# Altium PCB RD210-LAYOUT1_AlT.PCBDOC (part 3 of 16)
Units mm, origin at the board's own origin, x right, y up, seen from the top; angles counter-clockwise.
Board outline 330 x 300 mm, 6 copper layers (TOP, Mid-Layer 1, Mid-Layer 2, Mid-Layer 3, Mid-Layer 4, BOTTOM), stack 1.422 mm thick; 981 components, 463 nets, 2326 pads, 12534 vias.
Unrouted connection lines stored in the file: 6.
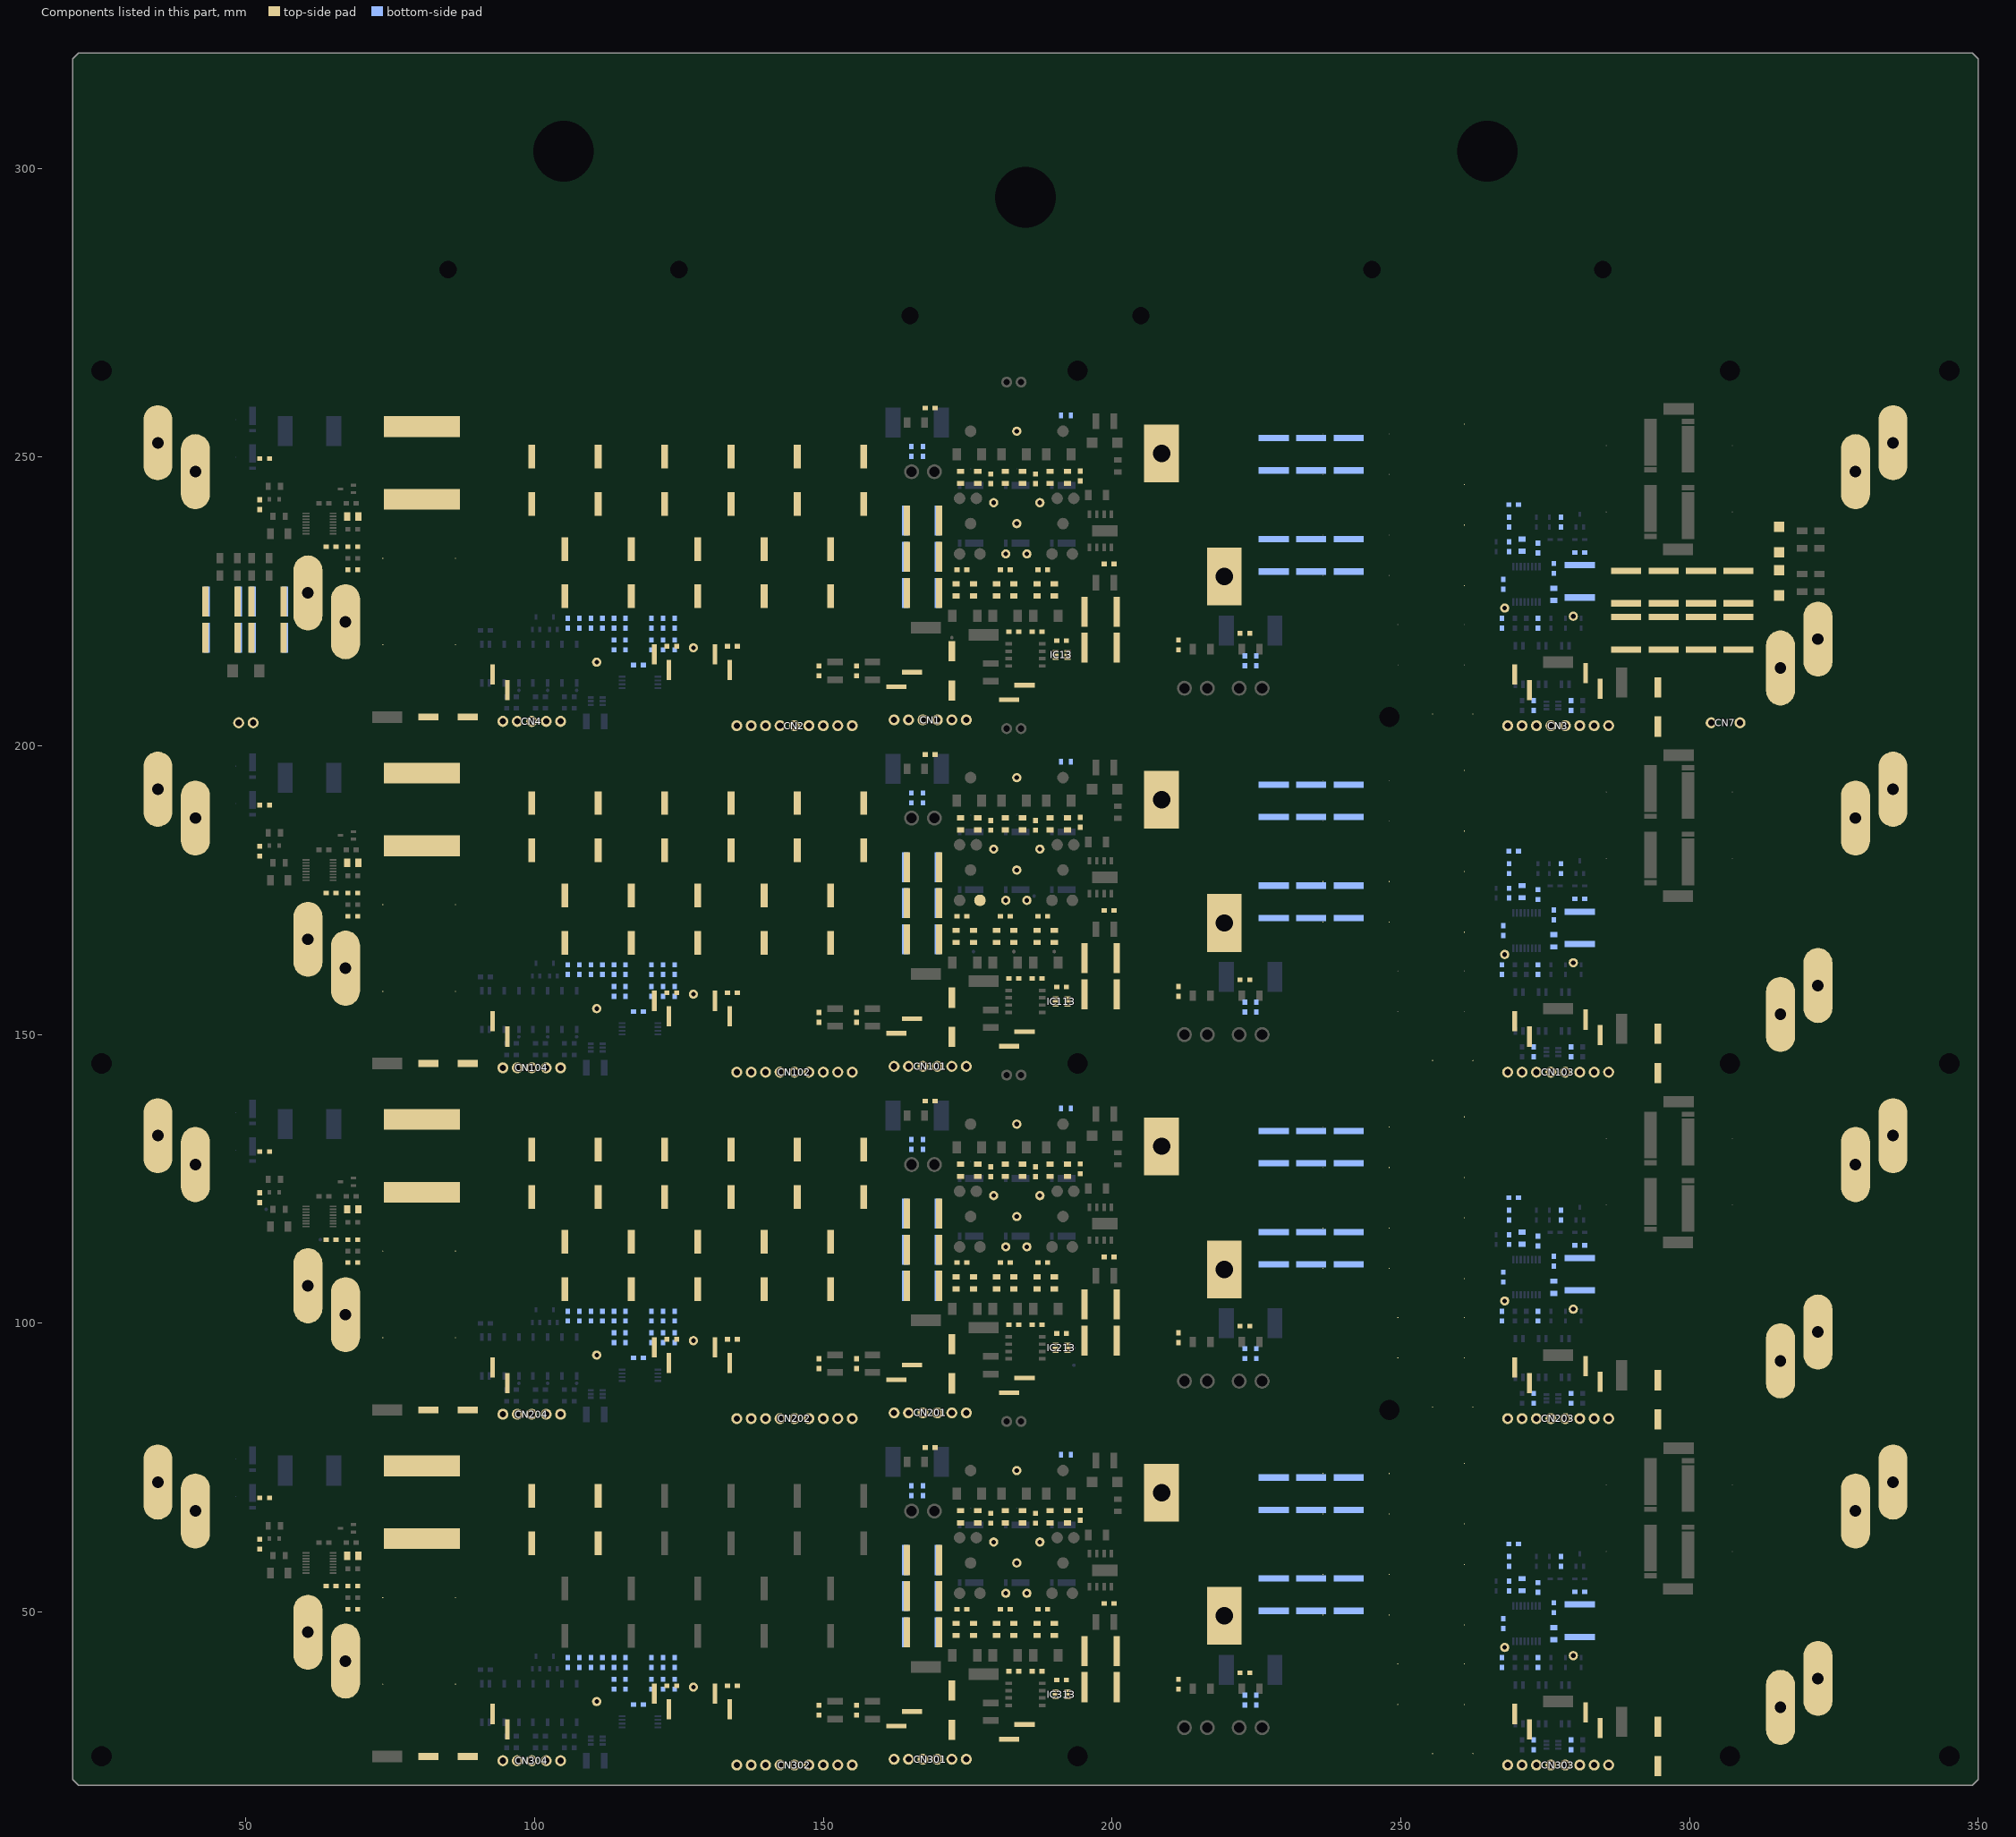
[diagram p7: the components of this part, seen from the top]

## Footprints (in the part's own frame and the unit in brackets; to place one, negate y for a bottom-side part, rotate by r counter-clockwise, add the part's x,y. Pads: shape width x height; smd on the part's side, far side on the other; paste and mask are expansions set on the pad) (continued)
_PCV1J390MCL2GS_+11 [mil] "KC00080BKP"
  round 7 smd paste-7 mask+0: 1(-137.8,0) 2(137.8,0)
_PCV1J390MCL2GS_+12 [mil] "KC00080BKP"
  round 7 smd paste-7 mask+0: 1(-137.8,0) 2(137.79,0)
_PCV1J390MCL2GS_+13 [mil] "KC00080BKP"
  round 7 smd paste-7 mask+0: 1(-137.8,0) 2(137.79,0)
_PCV1J390MCL2GS_+14 [mil] "KC00080BKP"
  round 7 smd paste-7 mask+0: 1(-137.79,0) 2(137.8,0)
_PCV1J390MCL2GS_+15 [mil] "KC00080BKP"
  round 7 smd paste-7 mask+0: 1(-137.79,0) 2(137.8,0)
_PCV1J390MCL2GS_+16 [mil] "KC00080BKP"
  round 7 smd paste-7 mask+0: 1(-137.79,0) 2(137.8,0)
_PCV1J390MCL2GS_+17 [mil] "KC00080BKP"
  round 7 smd paste-7 mask+0: 1(-137.79,0) 2(137.8,0)
_PCV1J390MCL2GS_+18 [mil] "KC00080BKP"
  round 7 smd paste-7 mask+0: 1(-137.79,0) 2(137.8,0)
_PCV1J390MCL2GS_+19 [mil] "KC00080BKP"
  round 7 smd paste-7 mask+0: 1(-137.79,0) 2(137.8,0)
_PCV1J390MCL2GS_+20 [mil] "KC00080BKP"
  round 7 smd paste-7 mask+0: 1(-137.79,0) 2(137.8,0)
_PCV1J390MCL2GS_+21 [mil] "KC00080BKP"
  round 7 smd paste-7 mask+0: 1(-137.79,0) 2(137.8,0)
_PCV1J390MCL2GS_+22 [mil] "KC00080BKP"
  round 7 smd paste-7 mask+0: 1(-137.8,0) 2(137.79,0)
_PCV1J390MCL2GS_+23 [mil] "KC00080BKP"
  round 7 smd paste-7 mask+0: 1(-137.8,0) 2(137.79,0)
_RK73B1JTTD103J_ [mm] "KC00080BKP"
  rect 0.9x0.8 smd paste-0.9 mask+0: 1(-0.85,0) 2(0.85,0)
_RK73B1JTTD103J_+1 [mm] "KC00080BKP"
  rect 0.9x0.8 smd paste-0.9 mask+0: 1(-0.85,0) 2(0.85,0)
_RK73B1JTTD103J_+2 [mm] "KC00080BKP"
  rect 0.9x0.8 smd paste-0.9 mask+0: 1(-0.85,0) 2(0.85,0)
_RK73B1JTTD103J_+3 [mm] "KC00080BKP"
  rect 0.9x0.8 smd paste-0.9 mask+0: 1(-0.85,0) 2(0.85,0)
_RK73B1JTTD103J_+4 [mm] "KC00080BKP"
  rect 0.9x0.8 smd paste-0.9 mask+0: 1(-0.85,0) 2(0.85,0)
_RK73B1JTTD103J_+5 [mm] "KC00080BKP"
  rect 0.9x0.8 smd paste-0.9 mask+0: 1(-0.85,0) 2(0.85,0)
_RK73B1JTTD103J_+6 [mm] "KC00080BKP"
  rect 0.9x0.8 smd paste-0.9 mask+0: 1(-0.85,0) 2(0.85,0)
_RK73B1JTTD103J_+7 [mm] "KC00080BKP"
  rect 0.9x0.8 smd paste-0.9 mask+0: 1(-0.85,0) 2(0.85,0)
_RK73B1JTTD103J_+8 [mm] "KC00080BKP"
  rect 0.9x0.8 smd paste-0.9 mask+0: 1(-0.85,0) 2(0.85,0)
_RK73B1JTTD103J_+9 [mm] "KC00080BKP"
  rect 0.9x0.8 smd paste-0.9 mask+0: 1(-0.85,0) 2(0.85,0)
_RK73B1JTTD103J_+10 [mm] "KC00080BKP"
  rect 0.9x0.8 smd paste-0.9 mask+0: 1(-0.85,0) 2(0.85,0)
_RK73B1JTTD103J_+11 [mm] "KC00080BKP"
  rect 0.9x0.8 smd paste-0.9 mask+0: 1(-0.85,0) 2(0.85,0)
_RK73B1JTTD103J_+12 [mm] "KC00080BKP"
  rect 0.9x0.8 smd paste-0.9 mask+0: 1(-0.85,0) 2(0.85,0)
_RK73B1JTTD103J_+13 [mm] "KC00080BKP"
  rect 0.9x0.8 smd paste-0.9 mask+0: 1(-0.85,0) 2(0.85,0)
_RK73B1JTTD103J_+14 [mm] "KC00080BKP"
  rect 0.9x0.8 smd paste-0.9 mask+0: 1(-0.85,0) 2(0.85,0)
_RK73B1JTTD103J_+15 [mm] "KC00080BKP"
  rect 0.9x0.8 smd paste-0.9 mask+0: 1(-0.85,0) 2(0.85,0)
_RK73B1JTTD103J_+16 [mm] "KC00080BKP"
  rect 0.9x0.8 smd paste-0.9 mask+0: 1(-0.85,0) 2(0.85,0)
_RK73B1JTTD103J_+17 [mm] "KC00080BKP"
  rect 0.9x0.8 smd paste-0.9 mask+0: 1(-0.85,0) 2(0.85,0)
_RK73B1JTTD103J_+18 [mm] "KC00080BKP"
  rect 0.9x0.8 smd paste-0.9 mask+0: 1(-0.85,0) 2(0.85,0)
_RK73B1JTTD103J_+19 [mm] "KC00080BKP"
  rect 0.9x0.8 smd paste-0.9 mask+0: 1(-0.85,0) 2(0.85,0)
_RK73B1JTTD103J_+20 [mm] "KC00080BKP"
  rect 0.9x0.8 smd paste-0.9 mask+0: 1(-0.85,0) 2(0.85,0)
_RK73B1JTTD103J_+21 [mm] "KC00080BKP"
  rect 0.9x0.8 smd paste-0.9 mask+0: 1(-0.85,0) 2(0.85,0)
_RK73B1JTTD103J_+22 [mm] "KC00080BKP"
  rect 0.9x0.8 smd paste-0.9 mask+0: 1(-0.85,0) 2(0.85,0)
_RK73B1JTTD103J_+23 [mm] "KC00080BKP"
  rect 0.9x0.8 smd paste-0.9 mask+0: 1(-0.85,0) 2(0.85,0)
_RK73B1JTTD222J_ [mm] "KC00080BKP"
  rect 0.9x0.8 smd paste-0.9 mask+0: 1(0.85,0) 2(-0.85,0)
_RK73B1JTTD222J_+1 [mm] "KC00080BKP"
  rect 0.9x0.8 smd paste-0.9 mask+0: 1(0.85,0) 2(-0.85,0)
_RK73B1JTTD222J_+2 [mm] "KC00080BKP"
  rect 0.9x0.8 smd paste-0.9 mask+0: 1(0.85,0) 2(-0.85,0)
_RK73B1JTTD222J_+3 [mm] "KC00080BKP"
  rect 0.9x0.8 smd paste-0.9 mask+0: 1(0.85,0) 2(-0.85,0)
_RK73B1JTTD222J_+4 [mm] "KC00080BKP"
  rect 0.9x0.8 smd paste-0.9 mask+0: 1(0.85,0) 2(-0.85,0)
_RK73B1JTTD222J_+5 [mm] "KC00080BKP"
  rect 0.9x0.8 smd paste-0.9 mask+0: 1(0.85,0) 2(-0.85,0)
_RK73B1JTTD222J_+6 [mm] "KC00080BKP"
  rect 0.9x0.8 smd paste-0.9 mask+0: 1(0.85,0) 2(-0.85,0)
_RK73B1JTTD222J_+7 [mm] "KC00080BKP"
  rect 0.9x0.8 smd paste-0.9 mask+0: 1(0.85,0) 2(-0.85,0)
_RK73B1JTTD334J_ [mm] "KC00080BKP"
  rect 0.9x0.8 smd paste-0.9 mask+0: 1(0.85,0) 2(-0.85,0)
_RK73B1JTTD334J_+1 [mm] "KC00080BKP"
  rect 0.9x0.8 smd paste-0.9 mask+0: 1(0.85,0) 2(-0.85,0)
_RK73B1JTTD334J_+2 [mm] "KC00080BKP"
  rect 0.9x0.8 smd paste-0.9 mask+0: 1(0.85,0) 2(-0.85,0)
_RK73B1JTTD334J_+3 [mm] "KC00080BKP"
  rect 0.9x0.8 smd paste-0.9 mask+0: 1(0.85,0) 2(-0.85,0)
_RK73B1JTTD473J_ [mm] "KC00080BKP"
  rect 0.9x0.8 smd paste-0.9 mask+0: 1(0.85,0) 2(-0.85,0)
_RK73B1JTTD473J_+1 [mm] "KC00080BKP"
  rect 0.9x0.8 smd paste-0.9 mask+0: 1(0.85,0) 2(-0.85,0)
_RK73B1JTTD473J_+2 [mm] "KC00080BKP"
  rect 0.9x0.8 smd paste-0.9 mask+0: 1(0.85,0) 2(-0.85,0)
_RK73B1JTTD473J_+3 [mm] "KC00080BKP"
  rect 0.9x0.8 smd paste-0.9 mask+0: 1(0.85,0) 2(-0.85,0)
_RK73B1JTTD473J_+4 [mm] "KC00080BKP"
  rect 0.9x0.8 smd paste-0.9 mask+0: 1(0.85,0) 2(-0.85,0)
_RK73B1JTTD473J_+5 [mm] "KC00080BKP"
  rect 0.9x0.8 smd paste-0.9 mask+0: 1(0.85,0) 2(-0.85,0)
_RK73B1JTTD473J_+6 [mm] "KC00080BKP"
  rect 0.9x0.8 smd paste-0.9 mask+0: 1(0.85,0) 2(-0.85,0)
_RK73B1JTTD473J_+7 [mm] "KC00080BKP"
  rect 0.9x0.8 smd paste-0.9 mask+0: 1(0.85,0) 2(-0.85,0)
_RK73G1JTTD10R0D_ [mm] "KC00080BKP"
  rect 0.9x0.8 smd paste-0.9 mask+0: 1(-0.85,0) 2(0.85,0)
_RK73G1JTTD10R0D_+1 [mm] "KC00080BKP"
  rect 0.9x0.8 smd paste-0.9 mask+0: 1(-0.85,0) 2(0.85,0)
_RK73G1JTTD10R0D_+2 [mm] "KC00080BKP"
  rect 0.9x0.8 smd paste-0.9 mask+0: 1(-0.85,0) 2(0.85,0)
_RK73G1JTTD10R0D_+3 [mm] "KC00080BKP"
  rect 0.9x0.8 smd paste-0.9 mask+0: 1(-0.85,0) 2(0.85,0)
_RK73G1JTTD10R0D_+4 [mm] "KC00080BKP"
  rect 0.9x0.8 smd paste-0.9 mask+0: 1(-0.85,0) 2(0.85,0)
_RK73G1JTTD10R0D_+5 [mm] "KC00080BKP"
  rect 0.9x0.8 smd paste-0.9 mask+0: 1(-0.85,0) 2(0.85,0)
_RK73G1JTTD10R0D_+6 [mm] "KC00080BKP"
  rect 0.9x0.8 smd paste-0.9 mask+0: 1(-0.85,0) 2(0.85,0)
_RK73G1JTTD10R0D_+7 [mm] "KC00080BKP"
  rect 0.9x0.8 smd paste-0.9 mask+0: 1(-0.85,0) 2(0.85,0)
_RK73G1JTTD1001D_ [mm] "KC00080BKP"
  rect 0.9x0.8 smd paste-0.9 mask+0: 1(0.85,0) 2(-0.85,0)
_RK73G1JTTD1001D_+1 [mm] "KC00080BKP"
  rect 0.9x0.8 smd paste-0.9 mask+0: 1(0.85,0) 2(-0.85,0)
_RK73G1JTTD1001D_+2 [mm] "KC00080BKP"
  rect 0.9x0.8 smd paste-0.9 mask+0: 1(0.85,0) 2(-0.85,0)
_RK73G1JTTD1001D_+3 [mm] "KC00080BKP"
  rect 0.9x0.8 smd paste-0.9 mask+0: 1(0.85,0) 2(-0.85,0)
_RK73G1JTTD1001D_+4 [mm] "KC00080BKP"
  rect 0.9x0.8 smd paste-0.9 mask+0: 1(0.85,0) 2(-0.85,0)
_RK73G1JTTD1001D_+5 [mm] "KC00080BKP"
  rect 0.9x0.8 smd paste-0.9 mask+0: 1(0.85,0) 2(-0.85,0)
_RK73G1JTTD1001D_+6 [mm] "KC00080BKP"
  rect 0.9x0.8 smd paste-0.9 mask+0: 1(0.85,0) 2(-0.85,0)
_RK73G1JTTD1001D_+7 [mm] "KC00080BKP"
  rect 0.9x0.8 smd paste-0.9 mask+0: 1(0.85,0) 2(-0.85,0)
_RK73G1JTTD1001D_+8 [mm] "KC00080BKP"
  rect 0.9x0.8 smd paste-0.9 mask+0: 1(0.85,0) 2(-0.85,0)
_RK73G1JTTD1001D_+9 [mm] "KC00080BKP"
  rect 0.9x0.8 smd paste-0.9 mask+0: 1(0.85,0) 2(-0.85,0)
_RK73G1JTTD1001D_+10 [mm] "KC00080BKP"
  rect 0.9x0.8 smd paste-0.9 mask+0: 1(0.85,0) 2(-0.85,0)
_RK73G1JTTD1001D_+11 [mm] "KC00080BKP"
  rect 0.9x0.8 smd paste-0.9 mask+0: 1(0.85,0) 2(-0.85,0)
_RK73G1JTTD1001D_+12 [mm] "KC00080BKP"
  rect 0.9x0.8 smd paste-0.9 mask+0: 1(0.85,0) 2(-0.85,0)
_RK73G1JTTD1001D_+13 [mm] "KC00080BKP"
  rect 0.9x0.8 smd paste-0.9 mask+0: 1(0.85,0) 2(-0.85,0)
_RK73G1JTTD1001D_+14 [mm] "KC00080BKP"
  rect 0.9x0.8 smd paste-0.9 mask+0: 1(0.85,0) 2(-0.85,0)
_RK73G1JTTD1001D_+15 [mm] "KC00080BKP"
  rect 0.9x0.8 smd paste-0.9 mask+0: 1(0.85,0) 2(-0.85,0)
_RK73G1JTTD1003D_ [mm] "KC00080BKP"
  rect 0.9x0.8 smd paste-0.9 mask+0: 1(-0.85,0) 2(0.85,0)
_RK73G1JTTD1003D_+1 [mm] "KC00080BKP"
  rect 0.9x0.8 smd paste-0.9 mask+0: 1(-0.85,0) 2(0.85,0)
_RK73G1JTTD1003D_+2 [mm] "KC00080BKP"
  rect 0.9x0.8 smd paste-0.9 mask+0: 1(-0.85,0) 2(0.85,0)
_RK73G1JTTD1003D_+3 [mm] "KC00080BKP"
  rect 0.9x0.8 smd paste-0.9 mask+0: 1(-0.85,0) 2(0.85,0)
_RK73G1JTTD1102D_ [mm] "KC00080BKP"
  rect 0.9x0.8 smd paste-0.9 mask+0: 1(0.85,0) 2(-0.85,0)
_RK73G1JTTD1102D_+1 [mm] "KC00080BKP"
  rect 0.9x0.8 smd paste-0.9 mask+0: 1(0.85,0) 2(-0.85,0)
_RK73G1JTTD1102D_+2 [mm] "KC00080BKP"
  rect 0.9x0.8 smd paste-0.9 mask+0: 1(0.85,0) 2(-0.85,0)
_RK73G1JTTD1102D_+3 [mm] "KC00080BKP"
  rect 0.9x0.8 smd paste-0.9 mask+0: 1(0.85,0) 2(-0.85,0)
_RK73G1JTTD1102D_+4 [mm] "KC00080BKP"
  rect 0.9x0.8 smd paste-0.9 mask+0: 1(0.85,0) 2(-0.85,0)
_RK73G1JTTD1102D_+5 [mm] "KC00080BKP"
  rect 0.9x0.8 smd paste-0.9 mask+0: 1(0.85,0) 2(-0.85,0)
_RK73G1JTTD1102D_+6 [mm] "KC00080BKP"
  rect 0.9x0.8 smd paste-0.9 mask+0: 1(0.85,0) 2(-0.85,0)
_RK73G1JTTD1102D_+7 [mm] "KC00080BKP"
  rect 0.9x0.8 smd paste-0.9 mask+0: 1(0.85,0) 2(-0.85,0)
_RK73G1JTTD1801D_ [mm] "KC00080BKP"
  rect 0.9x0.8 smd paste-0.9 mask+0: 1(-0.85,0) 2(0.85,0)
_RK73G1JTTD1801D_+1 [mm] "KC00080BKP"
  rect 0.9x0.8 smd paste-0.9 mask+0: 1(-0.85,0) 2(0.85,0)
_RK73G1JTTD1801D_+2 [mm] "KC00080BKP"
  rect 0.9x0.8 smd paste-0.9 mask+0: 1(-0.85,0) 2(0.85,0)
_RK73G1JTTD1801D_+3 [mm] "KC00080BKP"
  rect 0.9x0.8 smd paste-0.9 mask+0: 1(-0.85,0) 2(0.85,0)
_RK73G1JTTD2002D_ [mm] "KC00080BKP"
  rect 0.9x0.8 smd paste-0.9 mask+0: 1(0.85,0) 2(-0.85,0)
_RK73G1JTTD2002D_+1 [mm] "KC00080BKP"
  rect 0.9x0.8 smd paste-0.9 mask+0: 1(0.85,0) 2(-0.85,0)
_RK73G1JTTD2002D_+2 [mm] "KC00080BKP"
  rect 0.9x0.8 smd paste-0.9 mask+0: 1(0.85,0) 2(-0.85,0)
_RK73G1JTTD2002D_+3 [mm] "KC00080BKP"
  rect 0.9x0.8 smd paste-0.9 mask+0: 1(0.85,0) 2(-0.85,0)
_RK73G1JTTD2002D_+4 [mm] "KC00080BKP"
  rect 0.9x0.8 smd paste-0.9 mask+0: 1(0.85,0) 2(-0.85,0)
_RK73G1JTTD2002D_+5 [mm] "KC00080BKP"
  rect 0.9x0.8 smd paste-0.9 mask+0: 1(0.85,0) 2(-0.85,0)
_RK73G1JTTD2002D_+6 [mm] "KC00080BKP"
  rect 0.9x0.8 smd paste-0.9 mask+0: 1(0.85,0) 2(-0.85,0)
_RK73G1JTTD2002D_+7 [mm] "KC00080BKP"
  rect 0.9x0.8 smd paste-0.9 mask+0: 1(0.85,0) 2(-0.85,0)
_RK73G1JTTD2002D_+8 [mm] "KC00080BKP"
  rect 0.9x0.8 smd paste-0.9 mask+0: 1(0.85,0) 2(-0.85,0)
_RK73G1JTTD2002D_+9 [mm] "KC00080BKP"
  rect 0.9x0.8 smd paste-0.9 mask+0: 1(0.85,0) 2(-0.85,0)
_RK73G1JTTD2002D_+10 [mm] "KC00080BKP"
  rect 0.9x0.8 smd paste-0.9 mask+0: 1(0.85,0) 2(-0.85,0)
_RK73G1JTTD2002D_+11 [mm] "KC00080BKP"
  rect 0.9x0.8 smd paste-0.9 mask+0: 1(0.85,0) 2(-0.85,0)
_RK73G1JTTD2002D_+12 [mm] "KC00080BKP"
  rect 0.9x0.8 smd paste-0.9 mask+0: 1(0.85,0) 2(-0.85,0)
_RK73G1JTTD2002D_+13 [mm] "KC00080BKP"
  rect 0.9x0.8 smd paste-0.9 mask+0: 1(0.85,0) 2(-0.85,0)
_RK73G1JTTD2002D_+14 [mm] "KC00080BKP"
  rect 0.9x0.8 smd paste-0.9 mask+0: 1(0.85,0) 2(-0.85,0)
_RK73G1JTTD2002D_+15 [mm] "KC00080BKP"
  rect 0.9x0.8 smd paste-0.9 mask+0: 1(0.85,0) 2(-0.85,0)
_RK73H1JTTD1004F_ [mm] "KC00080BKP"
  rect 0.9x0.8 smd paste-0.9 mask+0: 1(-0.85,0) 2(0.85,0)
_RK73H1JTTD1004F_+1 [mm] "KC00080BKP"
  rect 0.9x0.8 smd paste-0.9 mask+0: 1(-0.85,0) 2(0.85,0)
_RK73H1JTTD1004F_+2 [mm] "KC00080BKP"
  rect 0.9x0.8 smd paste-0.9 mask+0: 1(-0.85,0) 2(0.85,0)
_RK73H1JTTD1004F_+3 [mm] "KC00080BKP"
  rect 0.9x0.8 smd paste-0.9 mask+0: 1(-0.85,0) 2(0.85,0)
_RK73H1JTTD3303F_ [mm] "KC00080BKP"
  rect 0.9x0.8 smd paste-0.9 mask+0: 1(0.85,0) 2(-0.85,0)
_RK73H1JTTD3303F_+1 [mm] "KC00080BKP"
  rect 0.9x0.8 smd paste-0.9 mask+0: 1(0.85,0) 2(-0.85,0)
_RK73H1JTTD3303F_+2 [mm] "KC00080BKP"
  rect 0.9x0.8 smd paste-0.9 mask+0: 1(0.85,0) 2(-0.85,0)
_RK73H1JTTD3303F_+3 [mm] "KC00080BKP"
  rect 0.9x0.8 smd paste-0.9 mask+0: 1(0.85,0) 2(-0.85,0)
_RK73H1JTTD6802F_ [mm] "KC00080BKP"
  rect 0.9x0.8 smd paste-0.9 mask+0: 1(-0.85,0) 2(0.85,0)
_RK73H1JTTD6802F_+1 [mm] "KC00080BKP"
  rect 0.9x0.8 smd paste-0.9 mask+0: 1(-0.85,0) 2(0.85,0)
_RK73H1JTTD6802F_+2 [mm] "KC00080BKP"
  rect 0.9x0.8 smd paste-0.9 mask+0: 1(-0.85,0) 2(0.85,0)
_RK73H1JTTD6802F_+3 [mm] "KC00080BKP"
  rect 0.9x0.8 smd paste-0.9 mask+0: 1(-0.85,0) 2(0.85,0)
_RK73Z1JTTD_ [mm] "KC00080BKP"
  rect 0.9x0.8 smd paste-0.9 mask+0: 1(-0.85,0) 2(0.85,0)
_RK73Z1JTTD_+1 [mm] "KC00080BKP"
  rect 0.9x0.8 smd paste-0.9 mask+0: 1(-0.85,0) 2(0.85,0)
_RK73Z1JTTD_+2 [mm] "KC00080BKP"
  rect 0.9x0.8 smd paste-0.9 mask+0: 1(-0.85,0) 2(0.85,0)
_RK73Z1JTTD_+3 [mm] "KC00080BKP"
  rect 0.9x0.8 smd paste-0.9 mask+0: 1(-0.85,0) 2(0.85,0)
_RK73Z1JTTD_+4 [mm] "KC00080BKP"
  rect 0.9x0.8 smd paste-0.9 mask+0: 1(-0.85,0) 2(0.85,0)
_RK73Z1JTTD_+5 [mm] "KC00080BKP"
  rect 0.9x0.8 smd paste-0.9 mask+0: 1(-0.85,0) 2(0.85,0)
_RK73Z1JTTD_+6 [mm] "KC00080BKP"
  rect 0.9x0.8 smd paste-0.9 mask+0: 1(-0.85,0) 2(0.85,0)
_RK73Z1JTTD_+7 [mm] "KC00080BKP"
  rect 0.9x0.8 smd paste-0.9 mask+0: 1(-0.85,0) 2(0.85,0)
_SG73P1JTTD473J_ [mm] "KC00080BKP"
  rect 0.9x0.8 smd paste-0.9 mask+0: 1(0.85,0) 2(-0.85,0)
_SG73P1JTTD473J_+1 [mm] "KC00080BKP"
  rect 0.9x0.8 smd paste-0.9 mask+0: 1(0.85,0) 2(-0.85,0)
_SG73P1JTTD473J_+2 [mm] "KC00080BKP"
  rect 0.9x0.8 smd paste-0.9 mask+0: 1(0.85,0) 2(-0.85,0)
_SG73P1JTTD473J_+3 [mm] "KC00080BKP"
  rect 0.9x0.8 smd paste-0.9 mask+0: 1(0.85,0) 2(-0.85,0)
_SG73P1JTTD473J_+4 [mm] "KC00080BKP"
  rect 0.9x0.8 smd paste-0.9 mask+0: 1(0.85,0) 2(-0.85,0)
_SG73P1JTTD473J_+5 [mm] "KC00080BKP"
  rect 0.9x0.8 smd paste-0.9 mask+0: 1(0.85,0) 2(-0.85,0)
_SG73P1JTTD473J_+6 [mm] "KC00080BKP"
  rect 0.9x0.8 smd paste-0.9 mask+0: 1(0.85,0) 2(-0.85,0)
_SG73P1JTTD473J_+7 [mm] "KC00080BKP"
  rect 0.9x0.8 smd paste-0.9 mask+0: 1(0.85,0) 2(-0.85,0)
_SG73P2ATTD1R0J_ [mm] "KC00080BKP"
  rect 0.9x1.25 smd paste-1.25 mask+0: 1(-1.05,0) 2(1.05,0)
_SG73P2ATTD1R0J_+1 [mm] "KC00080BKP"
  rect 0.9x1.25 smd paste-1.25 mask+0: 1(-1.05,0) 2(1.05,0)
_SG73P2ATTD1R0J_+2 [mm] "KC00080BKP"
  rect 0.9x1.25 smd paste-1.25 mask+0: 1(-1.05,0) 2(1.05,0)
_SG73P2ATTD1R0J_+3 [mm] "KC00080BKP"
  rect 0.9x1.25 smd paste-1.25 mask+0: 1(-1.05,0) 2(1.05,0)
_SG73P2ATTD1R0J_+4 [mm] "KC00080BKP"
  rect 0.9x1.25 smd paste-1.25 mask+0: 1(-1.05,0) 2(1.05,0)
_SG73P2ATTD1R0J_+5 [mm] "KC00080BKP"
  rect 0.9x1.25 smd paste-1.25 mask+0: 1(-1.05,0) 2(1.05,0)
_SG73P2ATTD1R0J_+6 [mm] "KC00080BKP"
  rect 0.9x1.25 smd paste-1.25 mask+0: 1(-1.05,0) 2(1.05,0)
_SG73P2ATTD1R0J_+7 [mm] "KC00080BKP"
  rect 0.9x1.25 smd paste-1.25 mask+0: 1(-1.05,0) 2(1.05,0)
_SG73P2ATTD1R0J_+8 [mm] "KC00080BKP"
  rect 0.9x1.25 smd paste-1.25 mask+0: 1(-1.05,0) 2(1.05,0)
_SG73P2ATTD1R0J_+9 [mm] "KC00080BKP"
  rect 0.9x1.25 smd paste-1.25 mask+0: 1(-1.05,0) 2(1.05,0)
_SG73P2ATTD1R0J_+10 [mm] "KC00080BKP"
  rect 0.9x1.25 smd paste-1.25 mask+0: 1(-1.05,0) 2(1.05,0)
_SG73P2ATTD1R0J_+11 [mm] "KC00080BKP"
  rect 0.9x1.25 smd paste-1.25 mask+0: 1(-1.05,0) 2(1.05,0)
_SG73P2ATTD1R0J_+12 [mm] "KC00080BKP"
  rect 0.9x1.25 smd paste-1.25 mask+0: 1(-1.05,0) 2(1.05,0)
_SG73P2ATTD1R0J_+13 [mm] "KC00080BKP"
  rect 0.9x1.25 smd paste-1.25 mask+0: 1(-1.05,0) 2(1.05,0)
_SG73P2ATTD1R0J_+14 [mm] "KC00080BKP"
  rect 0.9x1.25 smd paste-1.25 mask+0: 1(-1.05,0) 2(1.05,0)
_SG73P2ATTD1R0J_+15 [mm] "KC00080BKP"
  rect 0.9x1.25 smd paste-1.25 mask+0: 1(-1.05,0) 2(1.05,0)
_SG73P2ATTD1R0J_+16 [mm] "KC00080BKP"
  rect 0.9x1.25 smd paste-1.25 mask+0: 1(-1.05,0) 2(1.05,0)
_SG73P2ATTD1R0J_+17 [mm] "KC00080BKP"
  rect 0.9x1.25 smd paste-1.25 mask+0: 1(-1.05,0) 2(1.05,0)
_SG73P2ATTD1R0J_+18 [mm] "KC00080BKP"
  rect 0.9x1.25 smd paste-1.25 mask+0: 1(-1.05,0) 2(1.05,0)
_SG73P2ATTD1R0J_+19 [mm] "KC00080BKP"
  rect 0.9x1.25 smd paste-1.25 mask+0: 1(-1.05,0) 2(1.05,0)
_SG73P2ATTD1R0J_+20 [mm] "KC00080BKP"
  rect 0.9x1.25 smd paste-1.25 mask+0: 1(-1.05,0) 2(1.05,0)
_SG73P2ATTD1R0J_+21 [mm] "KC00080BKP"
  rect 0.9x1.25 smd paste-1.25 mask+0: 1(-1.05,0) 2(1.05,0)
_SG73P2ATTD1R0J_+22 [mm] "KC00080BKP"
  rect 0.9x1.25 smd paste-1.25 mask+0: 1(-1.05,0) 2(1.05,0)
_SG73P2ATTD1R0J_+23 [mm] "KC00080BKP"
  rect 0.9x1.25 smd paste-1.25 mask+0: 1(-1.05,0) 2(1.05,0)
_SG73P2ATTD2R2J_ [mm] "KC00080BKP"
  rect 0.9x1.25 smd paste-1.25 mask+0: 1(1.05,0) 2(-1.05,0)
_SG73P2ATTD2R2J_+1 [mm] "KC00080BKP"
  rect 0.9x1.25 smd paste-1.25 mask+0: 1(1.05,0) 2(-1.05,0)
_SG73P2ATTD2R2J_+2 [mm] "KC00080BKP"
  rect 0.9x1.25 smd paste-1.25 mask+0: 1(1.05,0) 2(-1.05,0)
_SG73P2ATTD2R2J_+3 [mm] "KC00080BKP"
  rect 0.9x1.25 smd paste-1.25 mask+0: 1(1.05,0) 2(-1.05,0)
_SG73P2ATTD100J_ [mm] "KC00080BKP"
  rect 0.9x1.25 smd paste-1.25 mask+0: 1(-1.05,0) 2(1.05,0)
_SG73P2ATTD100J_+1 [mm] "KC00080BKP"
  rect 0.9x1.25 smd paste-1.25 mask+0: 1(-1.05,0) 2(1.05,0)
_SG73P2ATTD100J_+2 [mm] "KC00080BKP"
  rect 0.9x1.25 smd paste-1.25 mask+0: 1(-1.05,0) 2(1.05,0)
_SG73P2ATTD100J_+3 [mm] "KC00080BKP"
  rect 0.9x1.25 smd paste-1.25 mask+0: 1(-1.05,0) 2(1.05,0)
_SG73P2ATTD100J_+4 [mm] "KC00080BKP"
  rect 0.9x1.25 smd paste-1.25 mask+0: 1(-1.05,0) 2(1.05,0)
_SG73P2ATTD100J_+5 [mm] "KC00080BKP"
  rect 0.9x1.25 smd paste-1.25 mask+0: 1(-1.05,0) 2(1.05,0)
_SG73P2ATTD100J_+6 [mm] "KC00080BKP"
  rect 0.9x1.25 smd paste-1.25 mask+0: 1(-1.05,0) 2(1.05,0)
_SG73P2ATTD100J_+7 [mm] "KC00080BKP"
  rect 0.9x1.25 smd paste-1.25 mask+0: 1(-1.05,0) 2(1.05,0)
_SG73P2ATTD100J_+8 [mm] "KC00080BKP"
  rect 0.9x1.25 smd paste-1.25 mask+0: 1(-1.05,0) 2(1.05,0)
_SG73P2ATTD100J_+9 [mm] "KC00080BKP"
  rect 0.9x1.25 smd paste-1.25 mask+0: 1(-1.05,0) 2(1.05,0)
_SG73P2ATTD100J_+10 [mm] "KC00080BKP"
  rect 0.9x1.25 smd paste-1.25 mask+0: 1(-1.05,0) 2(1.05,0)
_SG73P2ATTD100J_+11 [mm] "KC00080BKP"
  rect 0.9x1.25 smd paste-1.25 mask+0: 1(-1.05,0) 2(1.05,0)
_SG73P2ATTD100J_+12 [mm] "KC00080BKP"
  rect 0.9x1.25 smd paste-1.25 mask+0: 1(-1.05,0) 2(1.05,0)
_SG73P2ATTD100J_+13 [mm] "KC00080BKP"
  rect 0.9x1.25 smd paste-1.25 mask+0: 1(-1.05,0) 2(1.05,0)
_SG73P2ATTD100J_+14 [mm] "KC00080BKP"
  rect 0.9x1.25 smd paste-1.25 mask+0: 1(-1.05,0) 2(1.05,0)
_SG73P2ATTD100J_+15 [mm] "KC00080BKP"
  rect 0.9x1.25 smd paste-1.25 mask+0: 1(-1.05,0) 2(1.05,0)
_SG73P2ATTD100J_+16 [mm] "KC00080BKP"
  rect 0.9x1.25 smd paste-1.25 mask+0: 1(-1.05,0) 2(1.05,0)
_SG73P2ATTD100J_+17 [mm] "KC00080BKP"
  rect 0.9x1.25 smd paste-1.25 mask+0: 1(-1.05,0) 2(1.05,0)
_SG73P2ATTD100J_+18 [mm] "KC00080BKP"
  rect 0.9x1.25 smd paste-1.25 mask+0: 1(-1.05,0) 2(1.05,0)
_SG73P2ATTD100J_+19 [mm] "KC00080BKP"
  rect 0.9x1.25 smd paste-1.25 mask+0: 1(-1.05,0) 2(1.05,0)
_SG73P2ATTD100J_+20 [mm] "KC00080BKP"
  rect 0.9x1.25 smd paste-1.25 mask+0: 1(-1.05,0) 2(1.05,0)
_SG73P2ATTD100J_+21 [mm] "KC00080BKP"
  rect 0.9x1.25 smd paste-1.25 mask+0: 1(-1.05,0) 2(1.05,0)
_SG73P2ATTD100J_+22 [mm] "KC00080BKP"
  rect 0.9x1.25 smd paste-1.25 mask+0: 1(-1.05,0) 2(1.05,0)
_SG73P2ATTD100J_+23 [mm] "KC00080BKP"
  rect 0.9x1.25 smd paste-1.25 mask+0: 1(-1.05,0) 2(1.05,0)
_SG73P2ATTD912J_ [mm] "KC00080BKP"
  rect 0.9x1.25 smd paste-1.25 mask+0: 1(1.05,0) 2(-1.05,0)
_SG73P2ATTD912J_+1 [mm] "KC00080BKP"
  rect 0.9x1.25 smd paste-1.25 mask+0: 1(1.05,0) 2(-1.05,0)
_SG73P2ATTD912J_+2 [mm] "KC00080BKP"
  rect 0.9x1.25 smd paste-1.25 mask+0: 1(1.05,0) 2(-1.05,0)
_SG73P2ATTD912J_+3 [mm] "KC00080BKP"
  rect 0.9x1.25 smd paste-1.25 mask+0: 1(1.05,0) 2(-1.05,0)
_SZ1SMA24AT3G_ [mm] "KC00080BKP"
  rect 1.8x1.8 smd paste-1.8 mask+0: 1(-2.2,0) 2(2.2,0)
_SZ1SMA24AT3G_+1 [mm] "KC00080BKP"
  rect 1.8x1.8 smd paste-1.8 mask+0: 1(-2.2,0) 2(2.2,0)
_TC7PZ17FU_ [mm] "KC00080BKP"
  rect 0.45x1.05 smd paste-1.05 mask+0: 1(-0.65,-1.025) 2(0,-1.025) 3(0.65,-1.025) 4(0.65,1.025) 5(0,1.025) 6(-0.65,1.025)
_TC7PZ17FU_+1 [mm] "KC00080BKP"
  rect 0.45x1.05 smd paste-1.05 mask+0: 1(-0.65,-1.025) 2(0,-1.025) 3(0.65,-1.025) 4(0.65,1.025) 5(0,1.025) 6(-0.65,1.025)
_TC7PZ17FU_+2 [mm] "KC00080BKP"
  rect 0.45x1.05 smd paste-1.05 mask+0: 1(-0.65,-1.025) 2(0,-1.025) 3(0.65,-1.025) 4(0.65,1.025) 5(0,1.025) 6(-0.65,1.025)
_TC7PZ17FU_+3 [mm] "KC00080BKP"
  rect 0.45x1.05 smd paste-1.05 mask+0: 1(-0.65,-1.025) 2(0,-1.025) 3(0.65,-1.025) 4(0.65,1.025) 5(0,1.025) 6(-0.65,1.025)
_TD11-3H103FT_ [mm] "KC00080BKP"
  rect 0.7x1 smd paste-1 mask+0: 1(0.85,0) 2(-0.85,0)
_TD11-3H103FT_+1 [mm] "KC00080BKP"
  rect 0.7x1 smd paste-1 mask+0: 1(0.85,0) 2(-0.85,0)
_TD11-3H103FT_+2 [mm] "KC00080BKP"
  rect 0.7x1 smd paste-1 mask+0: 1(0.85,0) 2(-0.85,0)
_TD11-3H103FT_+3 [mm] "KC00080BKP"
  rect 0.7x1 smd paste-1 mask+0: 1(0.85,0) 2(-0.85,0)
_TSM-102-01-L-SV_ [mm] "KC00080BKP"
  rect 0.8x3.5 smd paste-3.5 mask+0: 1(-1.27,1.35) 2(1.27,-1.35)
_TSM-102-01-L-SV_+1 [mm] "KC00080BKP"
  rect 0.8x3.5 smd paste-3.5 mask+0: 1(-1.27,1.35) 2(1.27,-1.35)
_TSM-102-01-L-SV_+2 [mm] "KC00080BKP"
  rect 0.8x3.5 smd paste-3.5 mask+0: 1(-1.27,1.35) 2(1.27,-1.35)
_TSM-102-01-L-SV_+3 [mm] "KC00080BKP"
  rect 0.8x3.5 smd paste-3.5 mask+0: 1(-1.27,1.35) 2(1.27,-1.35)
_TSM-102-01-L-SV_+4 [mm] "KC00080BKP"
  rect 0.8x3.5 smd paste-3.5 mask+0: 1(-1.27,1.35) 2(1.27,-1.35)
_TSM-102-01-L-SV_+5 [mm] "KC00080BKP"
  rect 0.8x3.5 smd paste-3.5 mask+0: 1(-1.27,1.35) 2(1.27,-1.35)
_TSM-102-01-L-SV_+6 [mm] "KC00080BKP"
  rect 0.8x3.5 smd paste-3.5 mask+0: 1(-1.27,1.35) 2(1.27,-1.35)
_TSM-102-01-L-SV_+7 [mm] "KC00080BKP"
  rect 0.8x3.5 smd paste-3.5 mask+0: 1(-1.27,1.35) 2(1.27,-1.35)
_TSM-102-01-L-SV_+8 [mm] "KC00080BKP"
  rect 0.8x3.5 smd paste-3.5 mask+0: 1(-1.27,1.35) 2(1.27,-1.35)
_TSM-102-01-L-SV_+9 [mm] "KC00080BKP"
  rect 0.8x3.5 smd paste-3.5 mask+0: 1(-1.27,1.35) 2(1.27,-1.35)
_TSM-102-01-L-SV_+10 [mm] "KC00080BKP"
  rect 0.8x3.5 smd paste-3.5 mask+0: 1(-1.27,1.35) 2(1.27,-1.35)
_TSM-102-01-L-SV_+11 [mm] "KC00080BKP"
  rect 0.8x3.5 smd paste-3.5 mask+0: 1(-1.27,1.35) 2(1.27,-1.35)
_TSM-102-01-L-SV_+12 [mm] "KC00080BKP"
  rect 0.8x3.5 smd paste-3.5 mask+0: 1(-1.27,1.35) 2(1.27,-1.35)
_TSM-102-01-L-SV_+13 [mm] "KC00080BKP"
  rect 0.8x3.5 smd paste-3.5 mask+0: 1(-1.27,1.35) 2(1.27,-1.35)
_TSM-102-01-L-SV_+14 [mm] "KC00080BKP"
  rect 0.8x3.5 smd paste-3.5 mask+0: 1(-1.27,1.35) 2(1.27,-1.35)
_TSM-102-01-L-SV_+15 [mm] "KC00080BKP"
  rect 0.8x3.5 smd paste-3.5 mask+0: 1(-1.27,1.35) 2(1.27,-1.35)
_TSM-102-01-L-SV_+16 [mm] "KC00080BKP"
  rect 0.8x3.5 smd paste-3.5 mask+0: 1(-1.27,1.35) 2(1.27,-1.35)
_TSM-102-01-L-SV_+17 [mm] "KC00080BKP"
  rect 0.8x3.5 smd paste-3.5 mask+0: 1(-1.27,1.35) 2(1.27,-1.35)
_TSM-102-01-L-SV_+18 [mm] "KC00080BKP"
  rect 0.8x3.5 smd paste-3.5 mask+0: 1(-1.27,1.35) 2(1.27,-1.35)
_TSM-102-01-L-SV_+19 [mm] "KC00080BKP"
  rect 0.8x3.5 smd paste-3.5 mask+0: 1(-1.27,1.35) 2(1.27,-1.35)
_TSM-102-01-L-SV_+20 [mm] "KC00080BKP"
  rect 0.8x3.5 smd paste-3.5 mask+0: 1(-1.27,1.35) 2(1.27,-1.35)
_TSM-102-01-L-SV_+21 [mm] "KC00080BKP"
  rect 0.8x3.5 smd paste-3.5 mask+0: 1(-1.27,1.35) 2(1.27,-1.35)
_TSM-102-01-L-SV_+22 [mm] "KC00080BKP"
  rect 0.8x3.5 smd paste-3.5 mask+0: 1(-1.27,1.35) 2(1.27,-1.35)
_TSM-102-01-L-SV_+23 [mm] "KC00080BKP"
  rect 0.8x3.5 smd paste-3.5 mask+0: 1(-1.27,1.35) 2(1.27,-1.35)
_TSM-102-01-L-SV_+24 [mm] "KC00080BKP"
  rect 0.8x3.5 smd paste-3.5 mask+0: 1(-1.27,1.35) 2(1.27,-1.35)
_TSM-102-01-L-SV_+25 [mm] "KC00080BKP"
  rect 0.8x3.5 smd paste-3.5 mask+0: 1(-1.27,1.35) 2(1.27,-1.35)
_TSM-102-01-L-SV_+26 [mm] "KC00080BKP"
  rect 0.8x3.5 smd paste-3.5 mask+0: 1(-1.27,1.35) 2(1.27,-1.35)
_TSM-102-01-L-SV_+27 [mm] "KC00080BKP"
  rect 0.8x3.5 smd paste-3.5 mask+0: 1(-1.27,1.35) 2(1.27,-1.35)
_TSW-101-07-G-S_ [mm] "KC00080BKP"
  round 1.6 hole 0.8 paste-1.7 mask+0: 1(0,0)
_UCZ1A221MCL1GS_ [mm] "KC00080BKP"
  rect 3.5x1.2 smd paste-3.5 mask+0: 1(-3.4,0) 2(3.4,0)
_UCZ1A221MCL1GS_+1 [mm] "KC00080BKP"
  rect 3.5x1.2 smd paste-3.5 mask+0: 1(-3.4,0) 2(3.4,0)
_UCZ1A221MCL1GS_+2 [mm] "KC00080BKP"
  rect 3.5x1.2 smd paste-3.5 mask+0: 1(-3.4,0) 2(3.4,0)
_UCZ1A221MCL1GS_+3 [mm] "KC00080BKP"
  rect 3.5x1.2 smd paste-3.5 mask+0: 1(-3.4,0) 2(3.4,0)
_UCZ1A221MCL1GS_+4 [mm] "KC00080BKP"
  rect 3.5x1.2 smd paste-3.5 mask+0: 1(-3.4,0) 2(3.4,0)
_UCZ1A221MCL1GS_+5 [mm] "KC00080BKP"
  rect 3.5x1.2 smd paste-3.5 mask+0: 1(-3.4,0) 2(3.4,0)
_UCZ1A221MCL1GS_+6 [mm] "KC00080BKP"
  rect 3.5x1.2 smd paste-3.5 mask+0: 1(-3.4,0) 2(3.4,0)
_UCZ1A221MCL1GS_+7 [mm] "KC00080BKP"
  rect 3.5x1.2 smd paste-3.5 mask+0: 1(-3.4,0) 2(3.4,0)
_UCZ1A221MCL1GS_+8 [mm] "KC00080BKP"
  rect 3.5x1.2 smd paste-3.5 mask+0: 1(-3.4,0) 2(3.4,0)
_UCZ1A221MCL1GS_+9 [mm] "KC00080BKP"
  rect 3.5x1.2 smd paste-3.5 mask+0: 1(-3.4,0) 2(3.4,0)
_UCZ1A221MCL1GS_+10 [mm] "KC00080BKP"
  rect 3.5x1.2 smd paste-3.5 mask+0: 1(-3.4,0) 2(3.4,0)
_UCZ1A221MCL1GS_+11 [mm] "KC00080BKP"
  rect 3.5x1.2 smd paste-3.5 mask+0: 1(-3.4,0) 2(3.4,0)
_UCZ1C221MCL1GS_ [mil] "KC00080BKP"
  round 7 smd paste-7 mask+0: 1(-137.79,0) 2(137.8,0)
_UCZ1C221MCL1GS_+1 [mil] "KC00080BKP"
  round 7 smd paste-7 mask+0: 1(-137.79,0) 2(137.8,0)
_UCZ1C221MCL1GS_+2 [mil] "KC00080BKP"
  round 7 smd paste-7 mask+0: 1(-137.79,0) 2(137.8,0)
_UCZ1C221MCL1GS_+3 [mil] "KC00080BKP"
  round 7 smd paste-7 mask+0: 1(-137.79,0) 2(137.8,0)
_UCZ1J151MNQ1MS_ [mil] "KC00080BKP"
  round 7 smd paste-7 mask+0: 1(-206.69,0) 2(206.69,0)
_UCZ1J151MNQ1MS_+1 [mil] "KC00080BKP"
  round 7 smd paste-7 mask+0: 1(-206.69,0) 2(206.69,0)
_UCZ1J151MNQ1MS_+2 [mil] "KC00080BKP"
  round 7 smd paste-7 mask+0: 1(-206.69,0) 2(206.69,0)
_UCZ1J151MNQ1MS_+3 [mil] "KC00080BKP"
  round 7 smd paste-7 mask+0: 1(-206.69,0) 2(206.69,0)
_UCZ1J151MNQ1MS_+4 [mil] "KC00080BKP"
  round 7 smd paste-7 mask+0: 1(-206.69,0) 2(206.69,0)
_UCZ1J151MNQ1MS_+5 [mil] "KC00080BKP"
  round 7 smd paste-7 mask+0: 1(-206.69,0) 2(206.69,0)
_UCZ1J151MNQ1MS_+6 [mil] "KC00080BKP"
  round 7 smd paste-7 mask+0: 1(-206.69,0) 2(206.69,0)
_UCZ1J151MNQ1MS_+7 [mil] "KC00080BKP"
  round 7 smd paste-7 mask+0: 1(-206.69,0) 2(206.69,0)
_UCZ1K151MNS1MS_ [mil] "KC00080BKP"
  round 7 smd paste-7 mask+0: 1(-248.03,0) 2(248.03,0)
_UCZ1K151MNS1MS_+1 [mil] "KC00080BKP"
  round 7 smd paste-7 mask+0: 1(-248.03,0) 2(248.03,0)
_UCZ1K151MNS1MS_+2 [mil] "KC00080BKP"
  round 7 smd paste-7 mask+0: 1(-248.03,0) 2(248.03,0)
_UCZ1K151MNS1MS_+3 [mil] "KC00080BKP"
  round 7 smd paste-7 mask+0: 1(-248.03,0) 2(248.03,0)
_UCZ1K151MNS1MS_+4 [mil] "KC00080BKP"
  round 7 smd paste-7 mask+0: 1(-248.03,0) 2(248.03,0)
_UCZ1K151MNS1MS_+5 [mil] "KC00080BKP"
  round 7 smd paste-7 mask+0: 1(-248.03,0) 2(248.03,0)
_UCZ1K151MNS1MS_+6 [mil] "KC00080BKP"
  round 7 smd paste-7 mask+0: 1(-248.03,0) 2(248.03,0)
_UCZ1K151MNS1MS_+7 [mil] "KC00080BKP"
  round 7 smd paste-7 mask+0: 1(-248.03,0) 2(248.03,0)
_XAL1580-401MED_ [mm] "KC00080BKP"
  rect 3.6x13.2 smd paste-13.2 mask+0: 1(-6.3,0) 2(6.3,0)
_XAL1580-401MED_+1 [mm] "KC00080BKP"
  rect 3.6x13.2 smd paste-13.2 mask+0: 1(-6.3,0) 2(6.3,0)
_XAL1580-401MED_+2 [mm] "KC00080BKP"
  rect 3.6x13.2 smd paste-13.2 mask+0: 1(-6.3,0) 2(6.3,0)
_XAL1580-401MED_+3 [mm] "KC00080BKP"
  rect 3.6x13.2 smd paste-13.2 mask+0: 1(-6.3,0) 2(6.3,0)
D2P_CN-7.4x5.75x7-PX2.5-H1.1 [mm] "KC00080BKP"
  round 1.9 hole 1.1 paste-2 mask+0: 1(1.25,0) 2(-1.25,0)
D2P_L-38.1x21.9x39.4-PX21.33-PY10.87-H7x3 [mm] "KC00080BKP"
  rect 10x6 hole 3 square paste-10.1 mask+0: 1(-10.664,-5.434) 2(10.664,5.434)
D2P_TN-L-H2x10-2 [mm] "KC00080BKP"
  oval 5x13 hole 2 slot 10 at 90 deg paste-13.1 mask+0: 1(-3.25,2.5) 2(3.25,-2.5)
D2P_TN-R-H2x10-2 [mm] "KC00080BKP"
  oval 5x13 hole 2 slot 10 at 90 deg paste-13.1 mask+0: 1(-3.25,-2.5) 2(3.25,2.5)
D3P_CN-9.9x5.75x7-PX2.5-H1.1 [mm] "KC00080BKP"
  round 1.9 hole 1.1 paste-2 mask+0: 1(2.5,0) 3(-2.5,0)
  round 0 hole 1.1 unplated paste-1.5 mask+0: 2(0,0)
D5P_CN-14.9x5.75x7-PX2.5-H1.1 [mm] "KC00080BKP"
  round 1.9 hole 1.1 paste-2 mask+0: 1(5,0) 2(2.5,0) 3(0,0) 4(-2.5,0) 5(-5,0)
D6P_CN-17.4x5.75x7-PX2.5-H1.1 [mm] "KC00080BKP"
  round 1.9 hole 1.1 paste-2 mask+0: 1(6.25,0) 2(3.75,0) 3(1.25,0) 4(-1.25,0) 5(-3.75,0) 6(-6.25,0)
D8P_CN-22.4x5.75x7-PX2.5-H1.1 [mm] "KC00080BKP"
  round 1.9 hole 1.1 paste-2 mask+0: 1(8.75,0) 2(6.25,0) 3(3.75,0) 4(1.25,0) 5(-1.25,0) 6(-3.75,0) 7(-6.25,0) 8(-8.75,0)
D9P_CN-24.9x5.75x7-PX2.5-H1.1 [mm] "KC00080BKP"
  round 1.9 hole 1.1 paste-2 mask+0: 1(10,0) 2(7.5,0) 3(5,0) 4(2.5,0) 5(0,0) 6(-2.5,0) 7(-5,0) 8(-7.5,0) 9(-10,0)
S1P_CP-D2 [mm] "KC00080BKP"
  round 2 smd paste-2 mask+0: 1(0,0)
S2P_CC-1.6x0.8x0.8-PX1.6#1 [mm] "KC00080BKP"
  rect 0.9x0.8 smd paste-0.9 mask+0: 1(-0.85,0) 2(0.85,0)
S2P_CC-1.6x0.8x0.8-PX1.6#2 [mm] "KC00080BKP"
  rect 0.9x0.8 smd paste-0.9 mask+0: 1(0.85,0) 2(-0.85,0)
S2P_CC-1.6x0.8x0.8-PX1.6+1 [mm] "KC00080BKP"
  rect 0.9x0.8 smd paste-0.9 mask+0: 1(0.85,0) 2(-0.85,0)
S2P_CC-1.6x0.8x0.8-PX1.6+2 [mm] "KC00080BKP"
  rect 0.9x0.8 smd paste-0.9 mask+0: 1(0.85,0) 2(-0.85,0)
S2P_CC-1.6x0.8x0.8-PX1.6+3 [mm] "KC00080BKP"
  rect 0.9x0.8 smd paste-0.9 mask+0: 1(0.85,0) 2(-0.85,0)
S2P_CC-1.6x0.8x0.8-PX1.6+4 [mm] "KC00080BKP"
  rect 0.9x0.8 smd paste-0.9 mask+0: 1(0.85,0) 2(-0.85,0)
S2P_CC-1.6x0.8x0.8-PX1.6+5 [mm] "KC00080BKP"
  rect 0.9x0.8 smd paste-0.9 mask+0: 1(0.85,0) 2(-0.85,0)
S2P_CC-1.6x0.8x0.8-PX1.6+6 [mm] "KC00080BKP"
  rect 0.9x0.8 smd paste-0.9 mask+0: 1(-0.85,0) 2(0.85,0)
S2P_CC-1.6x0.8x0.8-PX1.6+7 [mm] "KC00080BKP"
  rect 0.9x0.8 smd paste-0.9 mask+0: 1(-0.85,0) 2(0.85,0)
S2P_CC-1.6x0.8x0.8-PX1.6+8 [mm] "KC00080BKP"
  rect 0.9x0.8 smd paste-0.9 mask+0: 1(-0.85,0) 2(0.85,0)
S2P_CC-1.6x0.8x0.8-PX1.6+9 [mm] "KC00080BKP"
  rect 0.9x0.8 smd paste-0.9 mask+0: 1(0.85,0) 2(-0.85,0)
S2P_CC-1.6x0.8x0.8-PX1.6+10 [mm] "KC00080BKP"
  rect 0.9x0.8 smd paste-0.9 mask+0: 1(0.85,0) 2(-0.85,0)
S2P_CC-1.6x0.8x0.8-PX1.6+11 [mm] "KC00080BKP"
  rect 0.9x0.8 smd paste-0.9 mask+0: 1(0.85,0) 2(-0.85,0)
S2P_CC-1.6x0.8x0.8-PX1.6+12 [mm] "KC00080BKP"
  rect 0.9x0.8 smd paste-0.9 mask+0: 1(0.85,0) 2(-0.85,0)
S2P_CC-1.6x0.8x0.8-PX1.6+13 [mm] "KC00080BKP"
  rect 0.9x0.8 smd paste-0.9 mask+0: 1(0.85,0) 2(-0.85,0)
S2P_CC-1.6x0.8x0.8-PX1.6+14 [mm] "KC00080BKP"
  rect 0.9x0.8 smd paste-0.9 mask+0: 1(0.85,0) 2(-0.85,0)
S2P_CC-1.6x0.8x0.8-PX1.6+15 [mm] "KC00080BKP"
  rect 0.9x0.8 smd paste-0.9 mask+0: 1(0.85,0) 2(-0.85,0)
S2P_CC-1.6x0.8x0.8-PX1.6+16 [mm] "KC00080BKP"
  rect 0.9x0.8 smd paste-0.9 mask+0: 1(-0.85,0) 2(0.85,0)
S2P_CC-1.6x0.8x0.8-PX1.6+17 [mm] "KC00080BKP"
  rect 0.9x0.8 smd paste-0.9 mask+0: 1(0.85,0) 2(-0.85,0)
S2P_CC-1.6x0.8x0.8-PX1.6+18 [mm] "KC00080BKP"
  rect 0.9x0.8 smd paste-0.9 mask+0: 1(0.85,0) 2(-0.85,0)
S2P_CC-1.6x0.8x0.8-PX1.6+19 [mm] "KC00080BKP"
  rect 0.9x0.8 smd paste-0.9 mask+0: 1(0.85,0) 2(-0.85,0)
S2P_CC-1.6x0.8x0.8-PX1.6+20 [mm] "KC00080BKP"
  rect 0.9x0.8 smd paste-0.9 mask+0: 1(0.85,0) 2(-0.85,0)
S2P_CC-1.6x0.8x0.8-PX1.6+21 [mm] "KC00080BKP"
  rect 0.9x0.8 smd paste-0.9 mask+0: 1(-0.85,0) 2(0.85,0)
S2P_CC-1.6x0.8x0.8-PX1.6+22 [mm] "KC00080BKP"
  rect 0.9x0.8 smd paste-0.9 mask+0: 1(-0.85,0) 2(0.85,0)
S2P_CC-1.6x0.8x0.8-PX1.6+23 [mm] "KC00080BKP"
  rect 0.9x0.8 smd paste-0.9 mask+0: 1(0.85,0) 2(-0.85,0)
S2P_CC-1.6x0.8x0.8-PX1.6+24 [mm] "KC00080BKP"
  rect 0.9x0.8 smd paste-0.9 mask+0: 1(0.85,0) 2(-0.85,0)
S2P_CC-1.6x0.8x0.8-PX1.6+25 [mm] "KC00080BKP"
  rect 0.9x0.8 smd paste-0.9 mask+0: 1(0.85,0) 2(-0.85,0)
S2P_CC-1.6x0.8x0.8-PX1.6+26 [mm] "KC00080BKP"
  rect 0.9x0.8 smd paste-0.9 mask+0: 1(-0.85,0) 2(0.85,0)
S2P_CC-1.6x0.8x0.8-PX1.6+27 [mm] "KC00080BKP"
  rect 0.9x0.8 smd paste-0.9 mask+0: 1(0.85,0) 2(-0.85,0)
S2P_CC-1.6x0.8x0.8-PX1.6+28 [mm] "KC00080BKP"
  rect 0.9x0.8 smd paste-0.9 mask+0: 1(0.85,0) 2(-0.85,0)
S2P_CC-1.6x0.8x0.8-PX1.6+29 [mm] "KC00080BKP"
  rect 0.9x0.8 smd paste-0.9 mask+0: 1(0.85,0) 2(-0.85,0)
S2P_CC-1.6x0.8x0.8-PX1.6+30 [mm] "KC00080BKP"
  rect 0.9x0.8 smd paste-0.9 mask+0: 1(0.85,0) 2(-0.85,0)
S2P_CC-1.6x0.8x0.8-PX1.6+31 [mm] "KC00080BKP"
  rect 0.9x0.8 smd paste-0.9 mask+0: 1(-0.85,0) 2(0.85,0)
S2P_CC-1.6x0.8x0.8-PX1.6+32 [mm] "KC00080BKP"
  rect 0.9x0.8 smd paste-0.9 mask+0: 1(-0.85,0) 2(0.85,0)
S2P_CC-1.6x0.8x0.8-PX1.6+33 [mm] "KC00080BKP"
  rect 0.9x0.8 smd paste-0.9 mask+0: 1(0.85,0) 2(-0.85,0)
S2P_CC-1.6x0.8x0.8-PX1.6+34 [mm] "KC00080BKP"
  rect 0.9x0.8 smd paste-0.9 mask+0: 1(0.85,0) 2(-0.85,0)
S2P_CC-1.6x0.8x0.8-PX1.6+35 [mm] "KC00080BKP"
  rect 0.9x0.8 smd paste-0.9 mask+0: 1(0.85,0) 2(-0.85,0)
S2P_CC-1.6x0.8x0.8-PX1.6+36 [mm] "KC00080BKP"
  rect 0.9x0.8 smd paste-0.9 mask+0: 1(0.85,0) 2(-0.85,0)
S2P_CC-1.6x0.8x0.8-PX1.6+37 [mm] "KC00080BKP"
  rect 0.9x0.8 smd paste-0.9 mask+0: 1(0.85,0) 2(-0.85,0)
S2P_CC-1.6x0.8x0.8-PX1.6+38 [mm] "KC00080BKP"
  rect 0.9x0.8 smd paste-0.9 mask+0: 1(0.85,0) 2(-0.85,0)
S2P_CC-1.6x0.8x0.8-PX1.6+39 [mm] "KC00080BKP"
  rect 0.9x0.8 smd paste-0.9 mask+0: 1(0.85,0) 2(-0.85,0)
S2P_CC-1.6x0.8x0.8-PX1.6+40 [mm] "KC00080BKP"
  rect 0.9x0.8 smd paste-0.9 mask+0: 1(0.85,0) 2(-0.85,0)
S2P_CC-1.6x0.8x0.8-PX1.6+41 [mm] "KC00080BKP"
  rect 0.9x0.8 smd paste-0.9 mask+0: 1(0.85,0) 2(-0.85,0)
S2P_CC-1.6x0.8x0.8-PX1.6+42 [mm] "KC00080BKP"
  rect 0.9x0.8 smd paste-0.9 mask+0: 1(0.85,0) 2(-0.85,0)
S2P_CC-1.6x0.8x0.8-PX1.6+43 [mm] "KC00080BKP"
  rect 0.9x0.8 smd paste-0.9 mask+0: 1(0.85,0) 2(-0.85,0)
S2P_CC-1.6x0.8x0.8-PX1.6+44 [mm] "KC00080BKP"
  rect 0.9x0.8 smd paste-0.9 mask+0: 1(0.85,0) 2(-0.85,0)
S2P_CC-1.6x0.8x0.8-PX1.6+45 [mm] "KC00080BKP"
  rect 0.9x0.8 smd paste-0.9 mask+0: 1(0.85,0) 2(-0.85,0)
S2P_CC-1.6x0.8x0.8-PX1.6+46 [mm] "KC00080BKP"
  rect 0.9x0.8 smd paste-0.9 mask+0: 1(0.85,0) 2(-0.85,0)
S2P_CC-1.6x0.8x0.8-PX1.6+47 [mm] "KC00080BKP"
  rect 0.9x0.8 smd paste-0.9 mask+0: 1(0.85,0) 2(-0.85,0)
S2P_CC-1.6x0.8x0.8-PX1.6+48 [mm] "KC00080BKP"
  rect 0.9x0.8 smd paste-0.9 mask+0: 1(0.85,0) 2(-0.85,0)
S2P_CC-1.6x0.8x0.8-PX1.6+49 [mm] "KC00080BKP"
  rect 0.9x0.8 smd paste-0.9 mask+0: 1(-0.85,0) 2(0.85,0)
S2P_CC-1.6x0.8x0.8-PX1.6+50 [mm] "KC00080BKP"
  rect 0.9x0.8 smd paste-0.9 mask+0: 1(-0.85,0) 2(0.85,0)
S2P_CC-1.6x0.8x0.8-PX1.6+51 [mm] "KC00080BKP"
  rect 0.9x0.8 smd paste-0.9 mask+0: 1(-0.85,0) 2(0.85,0)
S2P_CC-1.6x0.8x0.8-PX1.6+52 [mm] "KC00080BKP"
  rect 0.9x0.8 smd paste-0.9 mask+0: 1(0.85,0) 2(-0.85,0)
S2P_CC-1.6x0.8x0.8-PX1.6+53 [mm] "KC00080BKP"
  rect 0.9x0.8 smd paste-0.9 mask+0: 1(-0.85,0) 2(0.85,0)
S2P_CC-1.6x0.8x0.8-PX1.6+54 [mm] "KC00080BKP"
  rect 0.9x0.8 smd paste-0.9 mask+0: 1(-0.85,0) 2(0.85,0)
S2P_CC-1.6x0.8x0.8-PX1.6+55 [mm] "KC00080BKP"
  rect 0.9x0.8 smd paste-0.9 mask+0: 1(-0.85,0) 2(0.85,0)
S2P_CC-1.6x0.8x0.8-PX1.6+56 [mm] "KC00080BKP"
  rect 0.9x0.8 smd paste-0.9 mask+0: 1(0.85,0) 2(-0.85,0)
S2P_CC-1.6x0.8x0.8-PX1.6+57 [mm] "KC00080BKP"
  rect 0.9x0.8 smd paste-0.9 mask+0: 1(-0.85,0) 2(0.85,0)
S2P_CC-1.6x0.8x0.8-PX1.6+58 [mm] "KC00080BKP"
  rect 0.9x0.8 smd paste-0.9 mask+0: 1(-0.85,0) 2(0.85,0)
S2P_CC-1.6x0.8x0.8-PX1.6+59 [mm] "KC00080BKP"
  rect 0.9x0.8 smd paste-0.9 mask+0: 1(-0.85,0) 2(0.85,0)
S2P_CC-1.6x0.8x0.8-PX1.6+60 [mm] "KC00080BKP"
  rect 0.9x0.8 smd paste-0.9 mask+0: 1(0.85,0) 2(-0.85,0)
S2P_CC-1.6x0.8x0.8-PX1.6+61 [mm] "KC00080BKP"
  rect 0.9x0.8 smd paste-0.9 mask+0: 1(-0.85,0) 2(0.85,0)
S2P_CC-1.6x0.8x0.8-PX1.6+62 [mm] "KC00080BKP"
  rect 0.9x0.8 smd paste-0.9 mask+0: 1(-0.85,0) 2(0.85,0)
S2P_CC-1.6x0.8x0.8-PX1.6+63 [mm] "KC00080BKP"
  rect 0.9x0.8 smd paste-0.9 mask+0: 1(-0.85,0) 2(0.85,0)
S2P_CC-1.6x0.8x0.8-PX1.6+64 [mm] "KC00080BKP"
  rect 0.9x0.8 smd paste-0.9 mask+0: 1(0.85,0) 2(-0.85,0)
S2P_CC-1.6x0.8x0.8-PX1.6+65 [mm] "KC00080BKP"
  rect 0.9x0.8 smd paste-0.9 mask+0: 1(0.85,0) 2(-0.85,0)
S2P_CC-1.6x0.8x0.8-PX1.6+66 [mm] "KC00080BKP"
  rect 0.9x0.8 smd paste-0.9 mask+0: 1(0.85,0) 2(-0.85,0)
S2P_CC-1.6x0.8x0.8-PX1.6+67 [mm] "KC00080BKP"
  rect 0.9x0.8 smd paste-0.9 mask+0: 1(0.85,0) 2(-0.85,0)
S2P_CC-1.6x0.8x0.8-PX1.6+68 [mm] "KC00080BKP"
  rect 0.9x0.8 smd paste-0.9 mask+0: 1(0.85,0) 2(-0.85,0)
S2P_CC-1.6x0.8x0.8-PX1.6+69 [mm] "KC00080BKP"
  rect 0.9x0.8 smd paste-0.9 mask+0: 1(0.85,0) 2(-0.85,0)
S2P_CC-1.6x0.8x0.8-PX1.6+70 [mm] "KC00080BKP"
  rect 0.9x0.8 smd paste-0.9 mask+0: 1(-0.85,0) 2(0.85,0)
S2P_CC-1.6x0.8x0.8-PX1.6+71 [mm] "KC00080BKP"
  rect 0.9x0.8 smd paste-0.9 mask+0: 1(-0.85,0) 2(0.85,0)
S2P_CC-1.6x0.8x0.8-PX1.6+72 [mm] "KC00080BKP"
  rect 0.9x0.8 smd paste-0.9 mask+0: 1(-0.85,0) 2(0.85,0)
S2P_CC-1.6x0.8x0.8-PX1.6+73 [mm] "KC00080BKP"
  rect 0.9x0.8 smd paste-0.9 mask+0: 1(-0.85,0) 2(0.85,0)
S2P_CC-1.6x0.8x0.8-PX1.6+74 [mm] "KC00080BKP"
  rect 0.9x0.8 smd paste-0.9 mask+0: 1(-0.85,0) 2(0.85,0)
S2P_CC-1.6x0.8x0.8-PX1.6+75 [mm] "KC00080BKP"
  rect 0.9x0.8 smd paste-0.9 mask+0: 1(-0.85,0) 2(0.85,0)
S2P_CC-2x1.25x1.25-PX2 [mm] "KC00080BKP"
  rect 1.05x1.45 smd paste-1.45 mask+0: 1(-0.975,0) 2(0.975,0)
S2P_CC-2x1.25x1.25-PX2+1 [mm] "KC00080BKP"
  rect 1.05x1.45 smd paste-1.45 mask+0: 1(-0.975,0) 2(0.975,0)
S2P_CC-2x1.25x1.25-PX2+2 [mm] "KC00080BKP"
  rect 1.05x1.45 smd paste-1.45 mask+0: 1(-0.975,0) 2(0.975,0)
S2P_CC-2x1.25x1.25-PX2+3 [mm] "KC00080BKP"
  rect 1.05x1.45 smd paste-1.45 mask+0: 1(-0.975,0) 2(0.975,0)
S2P_CC-5.7x5x2.3-PX5.7 [mm] "KC00080BKP"
  rect 1.1x5.2 smd paste-5.2 mask+0: 1(-2.8,0) 2(2.8,0)
S2P_CC-5.7x5x2.3-PX5.7+1 [mm] "KC00080BKP"
  rect 1.1x5.2 smd paste-5.2 mask+0: 1(-2.8,0) 2(2.8,0)
S2P_CC-5.7x5x2.3-PX5.7+2 [mm] "KC00080BKP"
  rect 1.1x5.2 smd paste-5.2 mask+0: 1(-2.8,0) 2(2.8,0)
S2P_CC-5.7x5x2.3-PX5.7+3 [mm] "KC00080BKP"
  rect 1.1x5.2 smd paste-5.2 mask+0: 1(-2.8,0) 2(2.8,0)
S2P_CC-5.7x5x2.3-PX5.7+4 [mm] "KC00080BKP"
  rect 1.1x5.2 smd paste-5.2 mask+0: 1(2.8,0) 2(-2.8,0)
S2P_CC-5.7x5x2.3-PX5.7+5 [mm] "KC00080BKP"
  rect 1.1x5.2 smd paste-5.2 mask+0: 1(2.8,0) 2(-2.8,0)
S2P_CC-5.7x5x2.3-PX5.7+6 [mm] "KC00080BKP"
  rect 1.1x5.2 smd paste-5.2 mask+0: 1(2.8,0) 2(-2.8,0)
S2P_CC-5.7x5x2.3-PX5.7+7 [mm] "KC00080BKP"
  rect 1.1x5.2 smd paste-5.2 mask+0: 1(2.8,0) 2(-2.8,0)
S2P_CC-5.7x5x2.3-PX5.7+8 [mm] "KC00080BKP"
  rect 1.1x5.2 smd paste-5.2 mask+0: 1(-2.8,0) 2(2.8,0)
S2P_CC-5.7x5x2.3-PX5.7+9 [mm] "KC00080BKP"
  rect 1.1x5.2 smd paste-5.2 mask+0: 1(-2.8,0) 2(2.8,0)
S2P_CC-5.7x5x2.3-PX5.7+10 [mm] "KC00080BKP"
  rect 1.1x5.2 smd paste-5.2 mask+0: 1(-2.8,0) 2(2.8,0)
S2P_CC-5.7x5x2.3-PX5.7+11 [mm] "KC00080BKP"
  rect 1.1x5.2 smd paste-5.2 mask+0: 1(2.8,0) 2(-2.8,0)
S2P_CC-5.7x5x2.3-PX5.7+12 [mm] "KC00080BKP"
  rect 1.1x5.2 smd paste-5.2 mask+0: 1(-2.8,0) 2(2.8,0)
S2P_CC-5.7x5x2.3-PX5.7+13 [mm] "KC00080BKP"
  rect 1.1x5.2 smd paste-5.2 mask+0: 1(-2.8,0) 2(2.8,0)
S2P_CC-5.7x5x2.3-PX5.7+14 [mm] "KC00080BKP"
  rect 1.1x5.2 smd paste-5.2 mask+0: 1(-2.8,0) 2(2.8,0)
S2P_CC-5.7x5x2.3-PX5.7+15 [mm] "KC00080BKP"
  rect 1.1x5.2 smd paste-5.2 mask+0: 1(-2.8,0) 2(2.8,0)
S2P_CC-5.7x5x2.3-PX5.7+16 [mm] "KC00080BKP"
  rect 1.1x5.2 smd paste-5.2 mask+0: 1(-2.8,0) 2(2.8,0)
S2P_CC-5.7x5x2.3-PX5.7+17 [mm] "KC00080BKP"
  rect 1.1x5.2 smd paste-5.2 mask+0: 1(-2.8,0) 2(2.8,0)
S2P_CC-5.7x5x2.3-PX5.7+18 [mm] "KC00080BKP"
  rect 1.1x5.2 smd paste-5.2 mask+0: 1(-2.8,0) 2(2.8,0)
S2P_CC-5.7x5x2.3-PX5.7+19 [mm] "KC00080BKP"
  rect 1.1x5.2 smd paste-5.2 mask+0: 1(-2.8,0) 2(2.8,0)
S2P_CC-5.7x5x2.3-PX5.7+20 [mm] "KC00080BKP"
  rect 1.1x5.2 smd paste-5.2 mask+0: 1(-2.8,0) 2(2.8,0)
S2P_CC-5.7x5x2.3-PX5.7+21 [mm] "KC00080BKP"
  rect 1.1x5.2 smd paste-5.2 mask+0: 1(-2.8,0) 2(2.8,0)
S2P_CC-5.7x5x2.3-PX5.7+22 [mm] "KC00080BKP"
  rect 1.1x5.2 smd paste-5.2 mask+0: 1(-2.8,0) 2(2.8,0)
S2P_CC-5.7x5x2.3-PX5.7+23 [mm] "KC00080BKP"
  rect 1.1x5.2 smd paste-5.2 mask+0: 1(-2.8,0) 2(2.8,0)
S2P_CC-5.7x5x2.3-PX5.7+24 [mm] "KC00080BKP"
  rect 1.1x5.2 smd paste-5.2 mask+0: 1(-2.8,0) 2(2.8,0)
S2P_CC-5.7x5x2.3-PX5.7+25 [mm] "KC00080BKP"
  rect 1.1x5.2 smd paste-5.2 mask+0: 1(2.8,0) 2(-2.8,0)
S2P_CC-5.7x5x2.3-PX5.7+26 [mm] "KC00080BKP"
  rect 1.1x5.2 smd paste-5.2 mask+0: 1(2.8,0) 2(-2.8,0)
S2P_CC-5.7x5x2.3-PX5.7+27 [mm] "KC00080BKP"
  rect 1.1x5.2 smd paste-5.2 mask+0: 1(-2.8,0) 2(2.8,0)
S2P_CC-5.7x5x2.3-PX5.7+28 [mm] "KC00080BKP"
  rect 1.1x5.2 smd paste-5.2 mask+0: 1(-2.8,0) 2(2.8,0)
S2P_CC-5.7x5x2.3-PX5.7+29 [mm] "KC00080BKP"
  rect 1.1x5.2 smd paste-5.2 mask+0: 1(2.8,0) 2(-2.8,0)
S2P_CC-5.7x5x2.3-PX5.7+30 [mm] "KC00080BKP"
  rect 1.1x5.2 smd paste-5.2 mask+0: 1(2.8,0) 2(-2.8,0)
S2P_CC-5.7x5x2.3-PX5.7+31 [mm] "KC00080BKP"
  rect 1.1x5.2 smd paste-5.2 mask+0: 1(2.8,0) 2(-2.8,0)
S2P_CC-5.7x5x2.3-PX5.7+32 [mm] "KC00080BKP"
  rect 1.1x5.2 smd paste-5.2 mask+0: 1(2.8,0) 2(-2.8,0)
S2P_CC-5.7x5x2.3-PX5.7+33 [mm] "KC00080BKP"
  rect 1.1x5.2 smd paste-5.2 mask+0: 1(2.8,0) 2(-2.8,0)
S2P_CC-5.7x5x2.3-PX5.7+34 [mm] "KC00080BKP"
  rect 1.1x5.2 smd paste-5.2 mask+0: 1(2.8,0) 2(-2.8,0)
S2P_CC-5.7x5x2.3-PX5.7+35 [mm] "KC00080BKP"
  rect 1.1x5.2 smd paste-5.2 mask+0: 1(2.8,0) 2(-2.8,0)
S2P_CC-5.7x5x2.3-PX5.7+36 [mm] "KC00080BKP"
  rect 1.1x5.2 smd paste-5.2 mask+0: 1(-2.8,0) 2(2.8,0)
S2P_CC-5.7x5x2.3-PX5.7+37 [mm] "KC00080BKP"
  rect 1.1x5.2 smd paste-5.2 mask+0: 1(2.8,0) 2(-2.8,0)
S2P_CC-5.7x5x2.3-PX5.7+38 [mm] "KC00080BKP"
  rect 1.1x5.2 smd paste-5.2 mask+0: 1(2.8,0) 2(-2.8,0)
S2P_CC-5.7x5x2.3-PX5.7+39 [mm] "KC00080BKP"
  rect 1.1x5.2 smd paste-5.2 mask+0: 1(2.8,0) 2(-2.8,0)
S2P_CC-5.7x5x2.3-PX5.7+40 [mm] "KC00080BKP"
  rect 1.1x5.2 smd paste-5.2 mask+0: 1(-2.8,0) 2(2.8,0)
S2P_CC-5.7x5x2.3-PX5.7+41 [mm] "KC00080BKP"
  rect 1.1x5.2 smd paste-5.2 mask+0: 1(-2.8,0) 2(2.8,0)
S2P_CC-5.7x5x2.3-PX5.7+42 [mm] "KC00080BKP"
  rect 1.1x5.2 smd paste-5.2 mask+0: 1(2.8,0) 2(-2.8,0)
S2P_CC-5.7x5x2.3-PX5.7+43 [mm] "KC00080BKP"
  rect 1.1x5.2 smd paste-5.2 mask+0: 1(2.8,0) 2(-2.8,0)
S2P_CC-5.7x5x2.3-PX5.7+44 [mm] "KC00080BKP"
  rect 1.1x5.2 smd paste-5.2 mask+0: 1(2.8,0) 2(-2.8,0)
S2P_CC-5.7x5x2.3-PX5.7+45 [mm] "KC00080BKP"
  rect 1.1x5.2 smd paste-5.2 mask+0: 1(2.8,0) 2(-2.8,0)
S2P_CC-5.7x5x2.3-PX5.7+46 [mm] "KC00080BKP"
  rect 1.1x5.2 smd paste-5.2 mask+0: 1(2.8,0) 2(-2.8,0)
S2P_CC-5.7x5x2.3-PX5.7+47 [mm] "KC00080BKP"
  rect 1.1x5.2 smd paste-5.2 mask+0: 1(2.8,0) 2(-2.8,0)
S2P_CC-5.7x5x2.3-PX5.7+48 [mm] "KC00080BKP"
  rect 1.1x5.2 smd paste-5.2 mask+0: 1(2.8,0) 2(-2.8,0)
S2P_CC-5.7x5x2.3-PX5.7+49 [mm] "KC00080BKP"
  rect 1.1x5.2 smd paste-5.2 mask+0: 1(2.8,0) 2(-2.8,0)
S2P_CC-5.7x5x2.3-PX5.7+50 [mm] "KC00080BKP"
  rect 1.1x5.2 smd paste-5.2 mask+0: 1(2.8,0) 2(-2.8,0)
S2P_CC-5.7x5x2.3-PX5.7+51 [mm] "KC00080BKP"
  rect 1.1x5.2 smd paste-5.2 mask+0: 1(2.8,0) 2(-2.8,0)
S2P_CC-5.7x5x2.3-PX5.7+52 [mm] "KC00080BKP"
  rect 1.1x5.2 smd paste-5.2 mask+0: 1(-2.8,0) 2(2.8,0)
S2P_CC-5.7x5x2.3-PX5.7+53 [mm] "KC00080BKP"
  rect 1.1x5.2 smd paste-5.2 mask+0: 1(-2.8,0) 2(2.8,0)
S2P_CC-5.7x5x2.3-PX5.7+54 [mm] "KC00080BKP"
  rect 1.1x5.2 smd paste-5.2 mask+0: 1(2.8,0) 2(-2.8,0)
S2P_CC-5.7x5x2.3-PX5.7+55 [mm] "KC00080BKP"
  rect 1.1x5.2 smd paste-5.2 mask+0: 1(2.8,0) 2(-2.8,0)
S2P_CC-5.7x5x2.3-PX5.7+56 [mm] "KC00080BKP"
  rect 1.1x5.2 smd paste-5.2 mask+0: 1(2.8,0) 2(-2.8,0)
S2P_CC-5.7x5x2.3-PX5.7+57 [mm] "KC00080BKP"
  rect 1.1x5.2 smd paste-5.2 mask+0: 1(2.8,0) 2(-2.8,0)
S2P_CC-5.7x5x2.3-PX5.7+58 [mm] "KC00080BKP"
  rect 1.1x5.2 smd paste-5.2 mask+0: 1(2.8,0) 2(-2.8,0)
S2P_CC-5.7x5x2.3-PX5.7+59 [mm] "KC00080BKP"
  rect 1.1x5.2 smd paste-5.2 mask+0: 1(2.8,0) 2(-2.8,0)
S2P_CC-5.7x5x2.3-PX5.7+60 [mm] "KC00080BKP"
  rect 1.1x5.2 smd paste-5.2 mask+0: 1(2.8,0) 2(-2.8,0)
S2P_CC-5.7x5x2.3-PX5.7+61 [mm] "KC00080BKP"
  rect 1.1x5.2 smd paste-5.2 mask+0: 1(2.8,0) 2(-2.8,0)
S2P_CC-5.7x5x2.3-PX5.7+62 [mm] "KC00080BKP"
  rect 1.1x5.2 smd paste-5.2 mask+0: 1(2.8,0) 2(-2.8,0)
S2P_CC-5.7x5x2.3-PX5.7+63 [mm] "KC00080BKP"
  rect 1.1x5.2 smd paste-5.2 mask+0: 1(2.8,0) 2(-2.8,0)
S2P_CC-5.7x5x2.3-PX5.7+64 [mm] "KC00080BKP"
  rect 1.1x5.2 smd paste-5.2 mask+0: 1(2.8,0) 2(-2.8,0)
S2P_CC-5.7x5x2.3-PX5.7+65 [mm] "KC00080BKP"
  rect 1.1x5.2 smd paste-5.2 mask+0: 1(2.8,0) 2(-2.8,0)
S2P_CC-5.7x5x2.3-PX5.7+66 [mm] "KC00080BKP"
  rect 1.1x5.2 smd paste-5.2 mask+0: 1(2.8,0) 2(-2.8,0)
S2P_CC-5.7x5x2.3-PX5.7+67 [mm] "KC00080BKP"
  rect 1.1x5.2 smd paste-5.2 mask+0: 1(2.8,0) 2(-2.8,0)
S2P_CC-5.7x5x2.3-PX5.7+68 [mm] "KC00080BKP"
  rect 1.1x5.2 smd paste-5.2 mask+0: 1(2.8,0) 2(-2.8,0)
S2P_CC-5.7x5x2.3-PX5.7+69 [mm] "KC00080BKP"
  rect 1.1x5.2 smd paste-5.2 mask+0: 1(2.8,0) 2(-2.8,0)
S2P_CC-5.7x5x2.3-PX5.7+70 [mm] "KC00080BKP"
  rect 1.1x5.2 smd paste-5.2 mask+0: 1(2.8,0) 2(-2.8,0)
S2P_CC-5.7x5x2.3-PX5.7+71 [mm] "KC00080BKP"
  rect 1.1x5.2 smd paste-5.2 mask+0: 1(-2.8,0) 2(2.8,0)
S2P_CC-5.7x5x2.3-PX5.7+72 [mm] "KC00080BKP"
  rect 1.1x5.2 smd paste-5.2 mask+0: 1(-2.8,0) 2(2.8,0)
S2P_CC-5.7x5x2.3-PX5.7+73 [mm] "KC00080BKP"
  rect 1.1x5.2 smd paste-5.2 mask+0: 1(-2.8,0) 2(2.8,0)
S2P_CC-5.7x5x2.3-PX5.7+74 [mm] "KC00080BKP"
  rect 1.1x5.2 smd paste-5.2 mask+0: 1(-2.8,0) 2(2.8,0)
S2P_CC-5.7x5x2.3-PX5.7+75 [mm] "KC00080BKP"
  rect 1.1x5.2 smd paste-5.2 mask+0: 1(-2.8,0) 2(2.8,0)
S2P_CE-10.3x10.3x12.6-PX11 [mm] "KC00080BKP"
  rect 4.1x1.2 smd paste-4.1 mask+0: 1(-4.1,0) 2(4.1,0)
S2P_CE-10.3x10.3x12.6-PX11+1 [mm] "KC00080BKP"
  rect 4.1x1.2 smd paste-4.1 mask+0: 1(-4.1,0) 2(4.1,0)
S2P_CE-10.3x10.3x12.6-PX11+2 [mm] "KC00080BKP"
  rect 4.1x1.2 smd paste-4.1 mask+0: 1(-4.1,0) 2(4.1,0)
S2P_CE-10.3x10.3x12.6-PX11+3 [mm] "KC00080BKP"
  rect 4.1x1.2 smd paste-4.1 mask+0: 1(-4.1,0) 2(4.1,0)
S2P_CE-10.3x10.3x12.6-PX11+4 [mm] "KC00080BKP"
  rect 4.1x1.2 smd paste-4.1 mask+0: 1(-4.1,0) 2(4.1,0)
S2P_CE-10.3x10.3x12.6-PX11+5 [mm] "KC00080BKP"
  rect 4.1x1.2 smd paste-4.1 mask+0: 1(-4.1,0) 2(4.1,0)
S2P_CE-10.3x10.3x12.6-PX11+6 [mm] "KC00080BKP"
  rect 4.1x1.2 smd paste-4.1 mask+0: 1(-4.1,0) 2(4.1,0)
S2P_CE-10.3x10.3x12.6-PX11+7 [mm] "KC00080BKP"
  rect 4.1x1.2 smd paste-4.1 mask+0: 1(-4.1,0) 2(4.1,0)
S2P_CE-10.3x10.3x12.6-PX11+8 [mm] "KC00080BKP"
  rect 4.1x1.2 smd paste-4.1 mask+0: 1(-4.1,0) 2(4.1,0)
S2P_CE-10.3x10.3x12.6-PX11+9 [mm] "KC00080BKP"
  rect 4.1x1.2 smd paste-4.1 mask+0: 1(-4.1,0) 2(4.1,0)
S2P_CE-10.3x10.3x12.6-PX11+10 [mm] "KC00080BKP"
  rect 4.1x1.2 smd paste-4.1 mask+0: 1(-4.1,0) 2(4.1,0)
S2P_CE-10.3x10.3x12.6-PX11+11 [mm] "KC00080BKP"
  rect 4.1x1.2 smd paste-4.1 mask+0: 1(-4.1,0) 2(4.1,0)
S2P_CE-10.3x10.3x12.6-PX11+12 [mm] "KC00080BKP"
  rect 4.1x1.2 smd paste-4.1 mask+0: 1(-4.1,0) 2(4.1,0)
S2P_CE-10.3x10.3x12.6-PX11+13 [mm] "KC00080BKP"
  rect 4.1x1.2 smd paste-4.1 mask+0: 1(-4.1,0) 2(4.1,0)
S2P_CE-10.3x10.3x12.6-PX11+14 [mm] "KC00080BKP"
  rect 4.1x1.2 smd paste-4.1 mask+0: 1(-4.1,0) 2(4.1,0)
S2P_CE-10.3x10.3x12.6-PX11+15 [mm] "KC00080BKP"
  rect 4.1x1.2 smd paste-4.1 mask+0: 1(-4.1,0) 2(4.1,0)
S2P_CE-10.3x10.3x12.6-PX11+16 [mm] "KC00080BKP"
  rect 4.1x1.2 smd paste-4.1 mask+0: 1(-4.1,0) 2(4.1,0)
S2P_CE-10.3x10.3x12.6-PX11+17 [mm] "KC00080BKP"
  rect 4.1x1.2 smd paste-4.1 mask+0: 1(-4.1,0) 2(4.1,0)
S2P_CE-10.3x10.3x12.6-PX11+18 [mm] "KC00080BKP"
  rect 4.1x1.2 smd paste-4.1 mask+0: 1(-4.1,0) 2(4.1,0)
S2P_CE-10.3x10.3x12.6-PX11+19 [mm] "KC00080BKP"
  rect 4.1x1.2 smd paste-4.1 mask+0: 1(-4.1,0) 2(4.1,0)
S2P_CE-10.3x10.3x12.6-PX11+20 [mm] "KC00080BKP"
  rect 4.1x1.2 smd paste-4.1 mask+0: 1(-4.1,0) 2(4.1,0)
S2P_CE-10.3x10.3x12.6-PX11+21 [mm] "KC00080BKP"
  rect 4.1x1.2 smd paste-4.1 mask+0: 1(-4.1,0) 2(4.1,0)
S2P_CE-10.3x10.3x12.6-PX11+22 [mm] "KC00080BKP"
  rect 4.1x1.2 smd paste-4.1 mask+0: 1(-4.1,0) 2(4.1,0)
S2P_CE-10.3x10.3x12.6-PX11+23 [mm] "KC00080BKP"
  rect 4.1x1.2 smd paste-4.1 mask+0: 1(-4.1,0) 2(4.1,0)
S2P_CE-10.3x10.3x12.6-PX11+24 [mm] "KC00080BKP"
  rect 4.1x1.2 smd paste-4.1 mask+0: 1(-4.1,0) 2(4.1,0)
S2P_CE-10.3x10.3x12.6-PX11+25 [mm] "KC00080BKP"
  rect 4.1x1.2 smd paste-4.1 mask+0: 1(-4.1,0) 2(4.1,0)
S2P_CE-10.3x10.3x12.6-PX11+26 [mm] "KC00080BKP"
  rect 4.1x1.2 smd paste-4.1 mask+0: 1(-4.1,0) 2(4.1,0)
S2P_CE-10.3x10.3x12.6-PX11+27 [mm] "KC00080BKP"
  rect 4.1x1.2 smd paste-4.1 mask+0: 1(-4.1,0) 2(4.1,0)
S2P_CE-10.3x10.3x12.6-PX11+28 [mm] "KC00080BKP"
  rect 4.1x1.2 smd paste-4.1 mask+0: 1(-4.1,0) 2(4.1,0)
S2P_CE-10.3x10.3x12.6-PX11+29 [mm] "KC00080BKP"
  rect 4.1x1.2 smd paste-4.1 mask+0: 1(-4.1,0) 2(4.1,0)
S2P_CE-10.3x10.3x12.6-PX11+30 [mm] "KC00080BKP"
  rect 4.1x1.2 smd paste-4.1 mask+0: 1(-4.1,0) 2(4.1,0)
S2P_CE-10.3x10.3x12.6-PX11+31 [mm] "KC00080BKP"
  rect 4.1x1.2 smd paste-4.1 mask+0: 1(-4.1,0) 2(4.1,0)
S2P_CE-10.3x10.3x12.6-PX11+32 [mm] "KC00080BKP"
  rect 4.1x1.2 smd paste-4.1 mask+0: 1(-4.1,0) 2(4.1,0)
S2P_CE-10.3x10.3x12.6-PX11+33 [mm] "KC00080BKP"
  rect 4.1x1.2 smd paste-4.1 mask+0: 1(-4.1,0) 2(4.1,0)
S2P_CE-10.3x10.3x12.6-PX11+34 [mm] "KC00080BKP"
  rect 4.1x1.2 smd paste-4.1 mask+0: 1(-4.1,0) 2(4.1,0)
